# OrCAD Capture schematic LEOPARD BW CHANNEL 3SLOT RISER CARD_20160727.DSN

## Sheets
1 010 HISTORY: title: 010 HISTORY; rev: SA; company: Wiwynn Corporation; note: LEOPARD BDW RISER CARD; note: 8F, No.90, Xintai 5th Rd., Xizhi Dist,; note: New Taipei, Taiwan
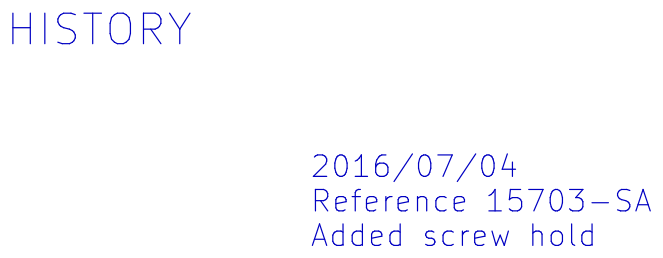
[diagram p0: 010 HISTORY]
2 009 P3V3_TPS53319: size A2; title: 009 P3V3_TPS53319; note: LEOPARD BW CHANNEL RISER CARD
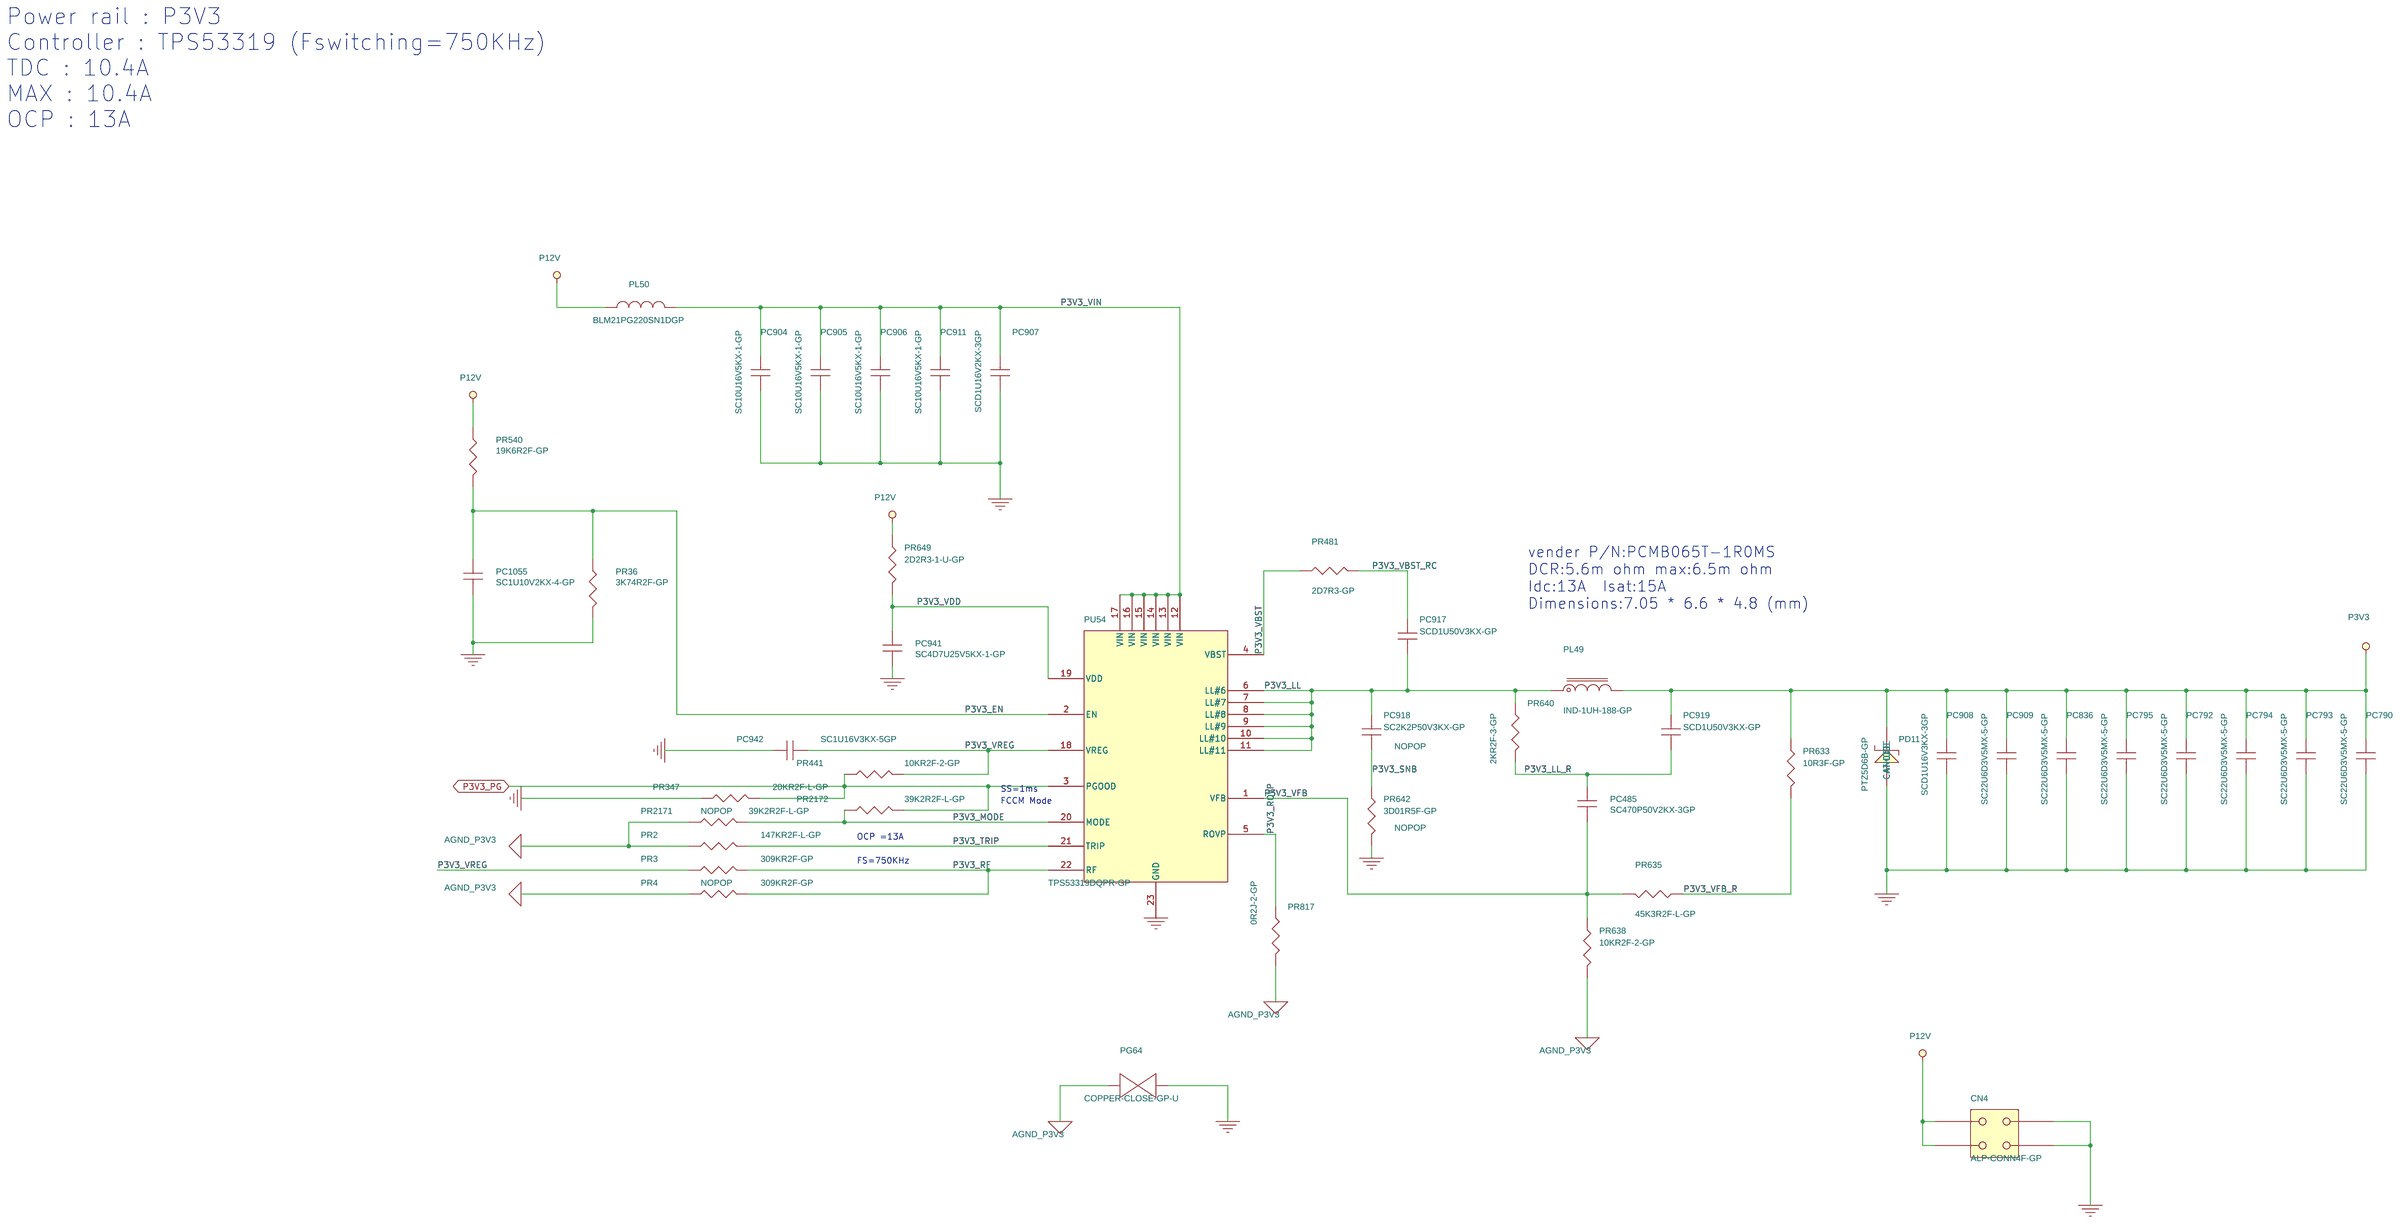
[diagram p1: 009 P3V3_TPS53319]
3 008 I2C-bus multiplexer: size A4; title: 008 I2C-Bus Multiplexer; note: LEOPARD BW CHANNEL RISER CARD
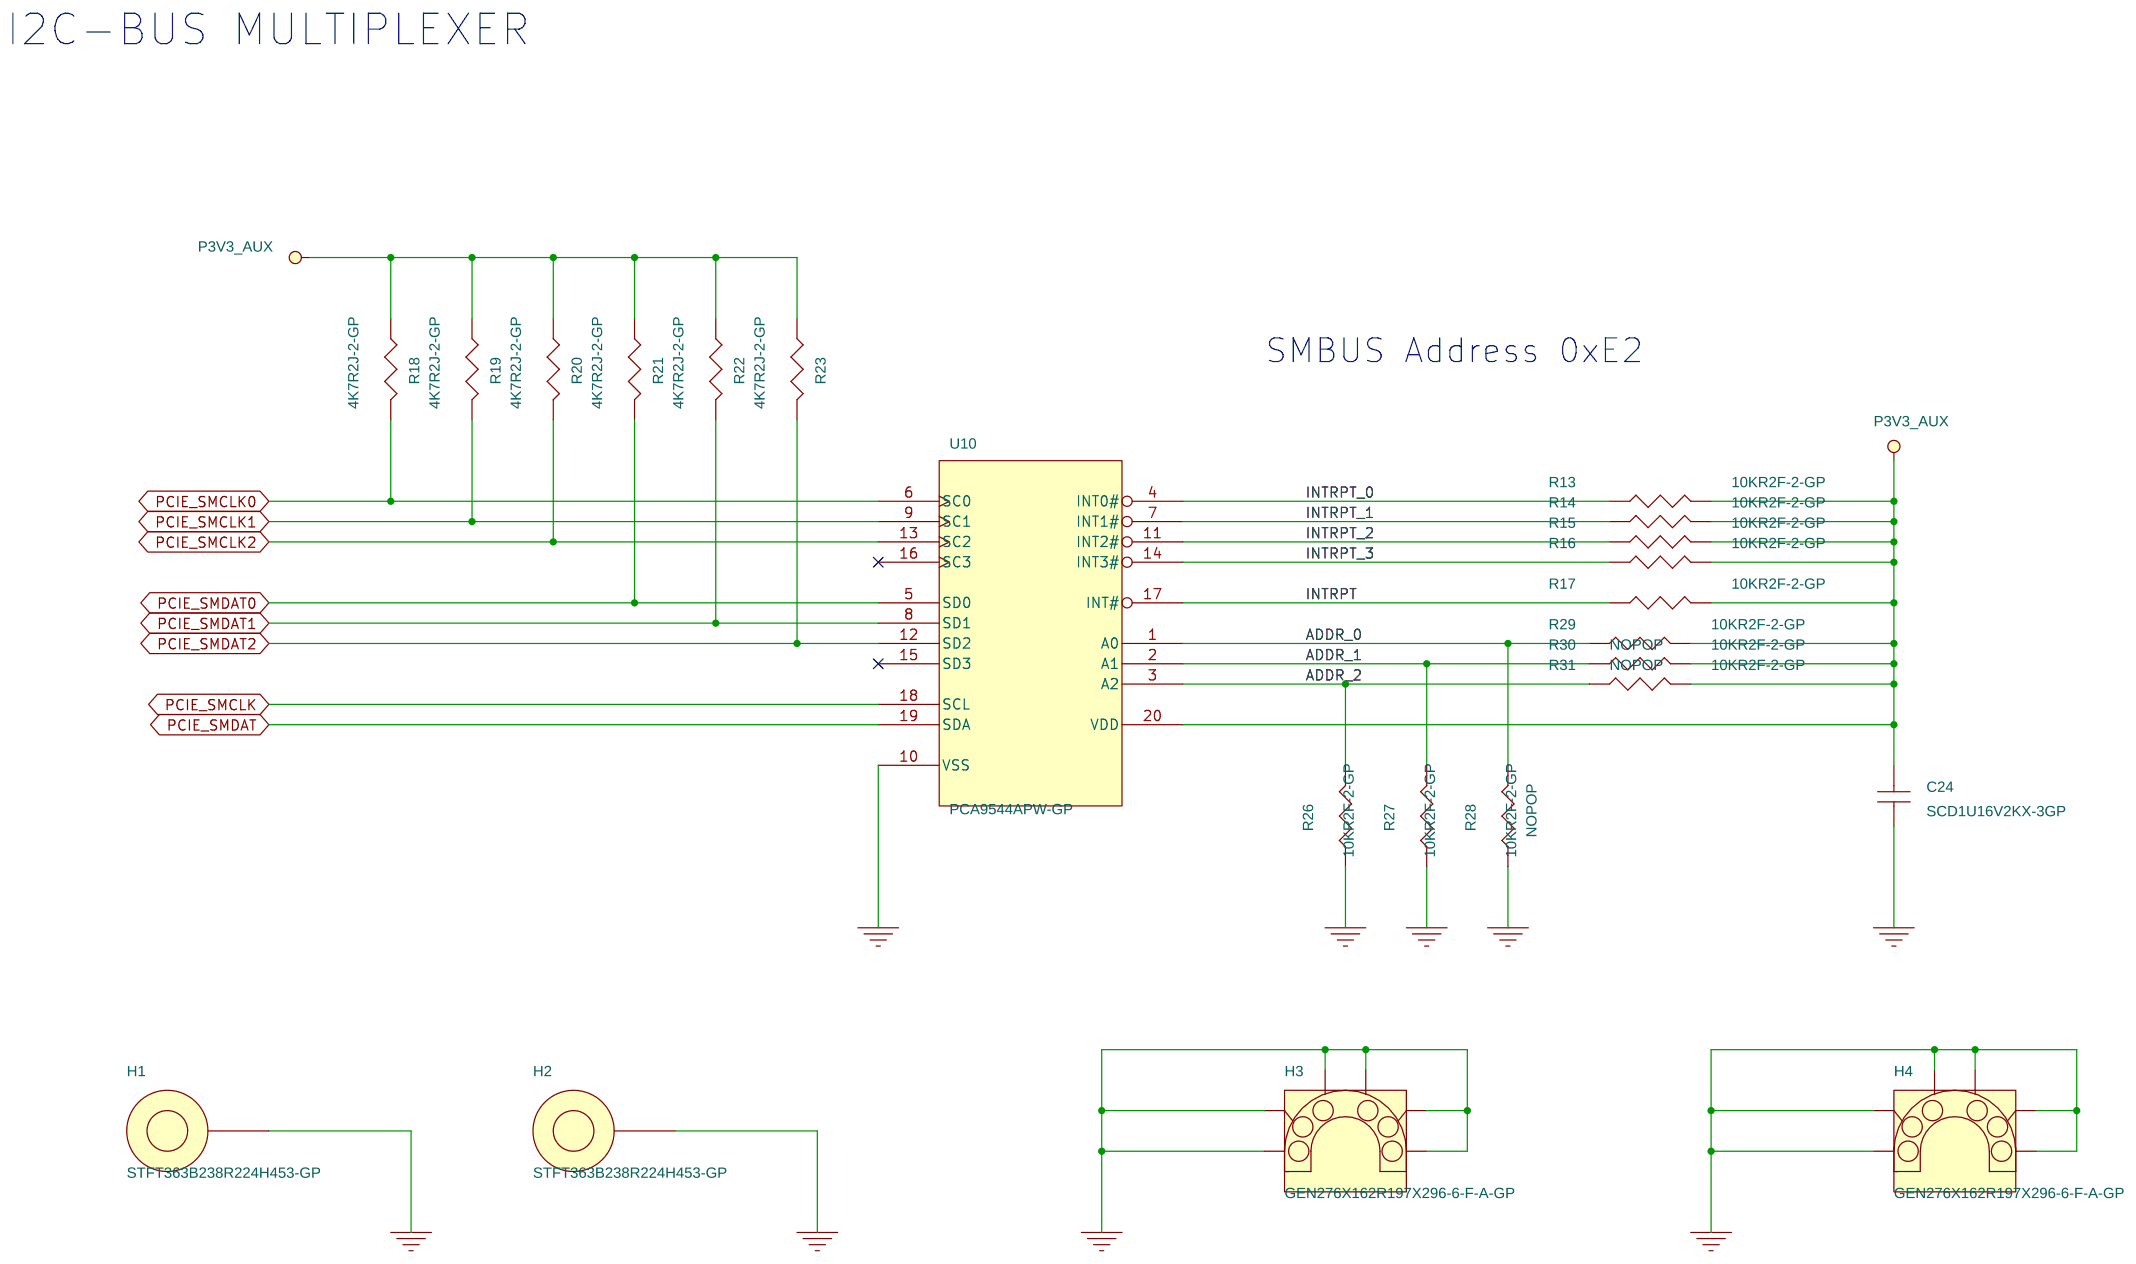
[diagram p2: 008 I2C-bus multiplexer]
4 007 PCIE X24 RISER GF: size A2; title: 007 PCIE X24 RISER GF; note: LEOPARD BW CHANNEL RISER CARD
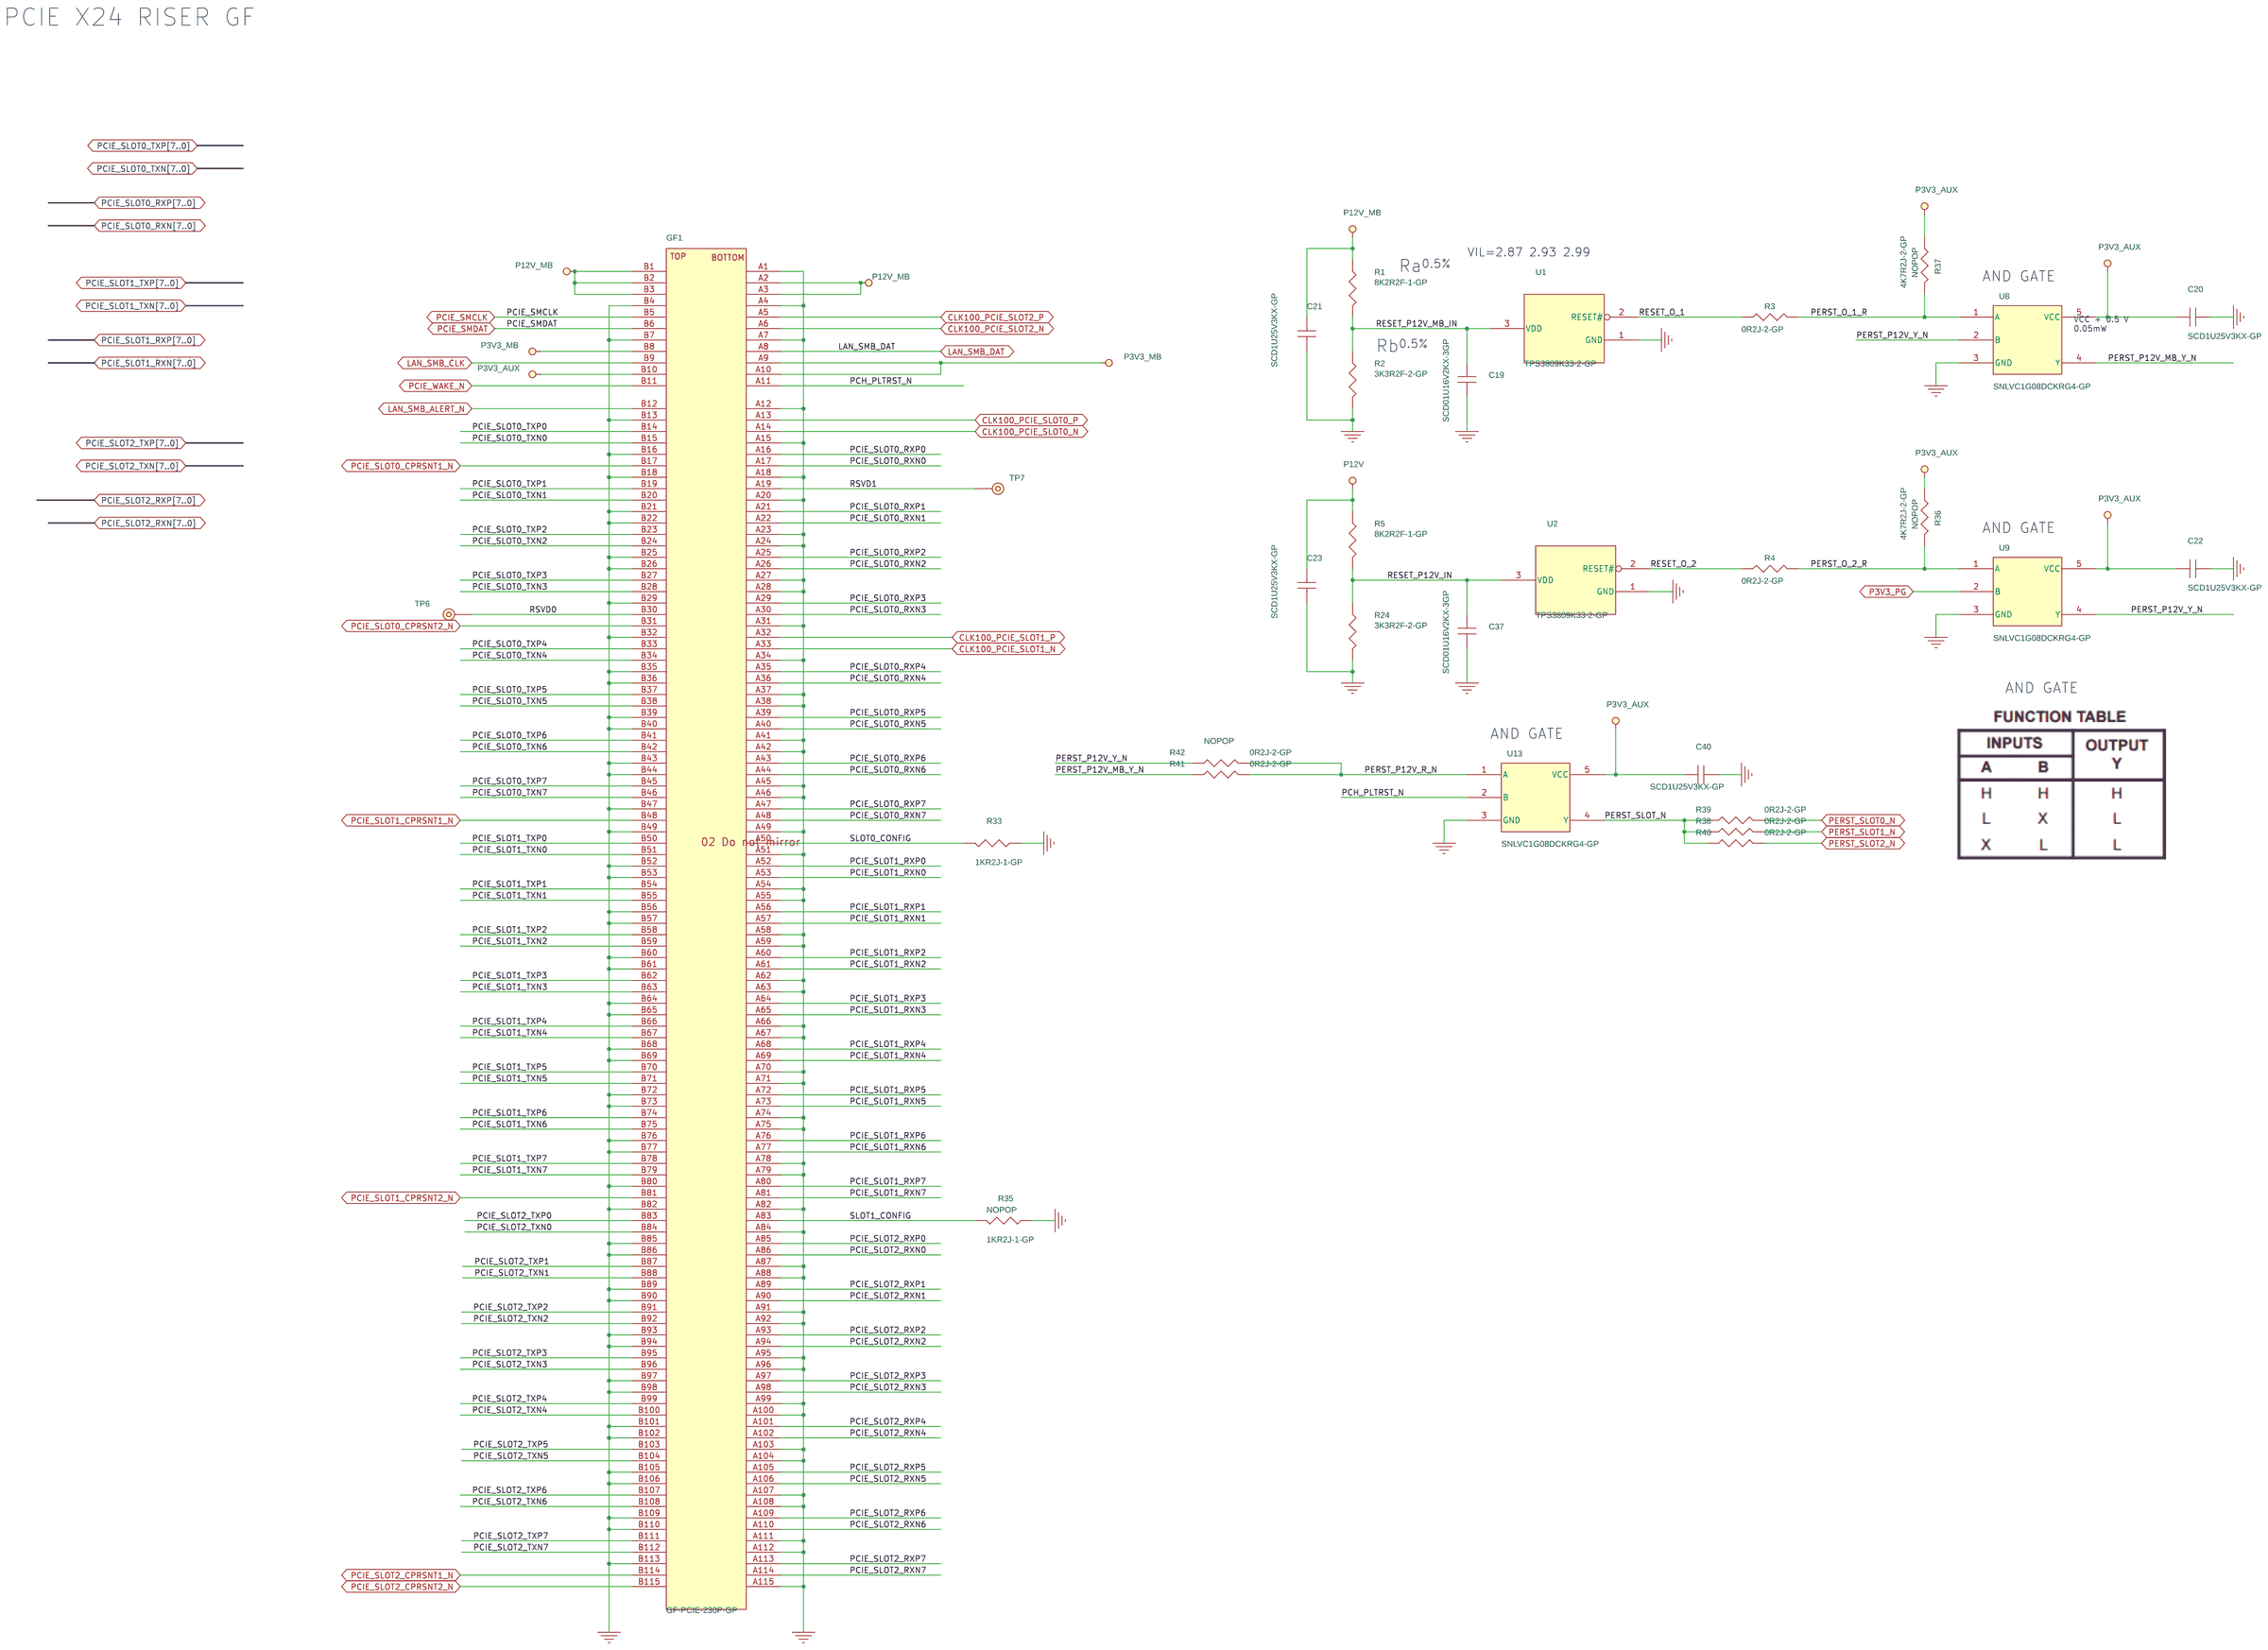
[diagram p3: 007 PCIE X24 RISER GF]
5 006 PCIE X8 RISER SLOT2: size A3; title: 006 PCIE X8 RISER SLOT4; note: LEOPARD BW CHANNEL RISER CARD
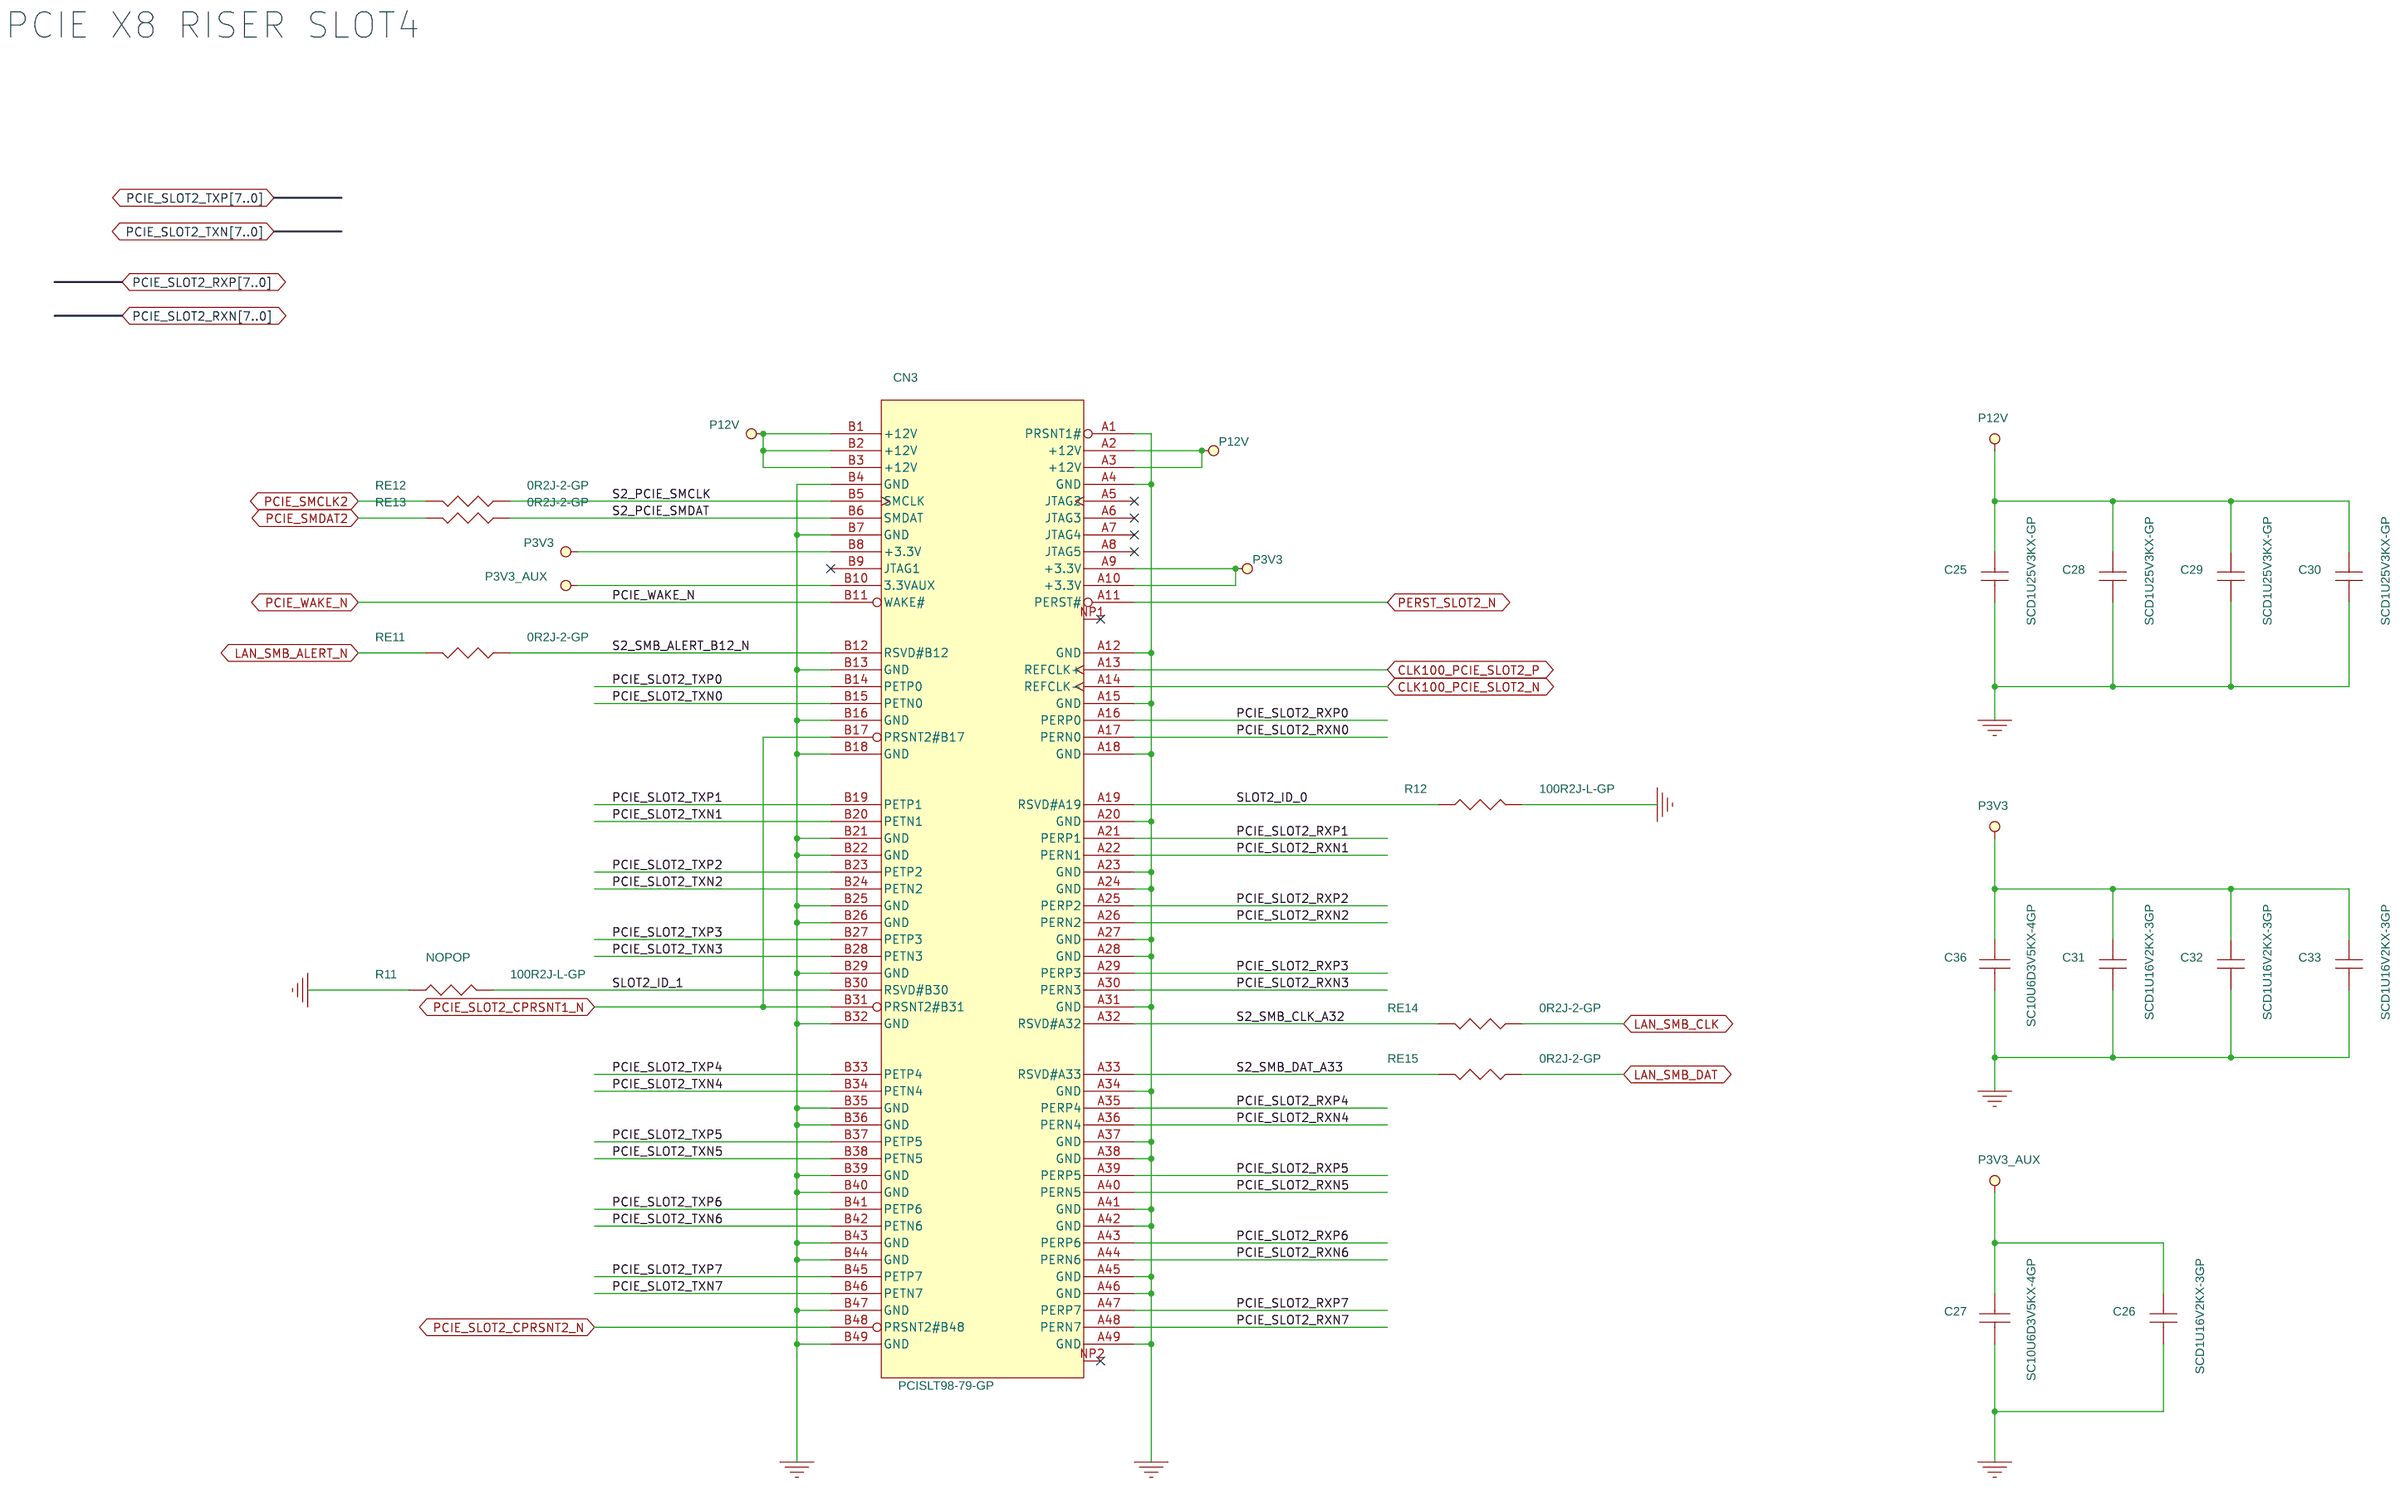
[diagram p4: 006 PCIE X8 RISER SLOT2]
6 005 PCIE X8 RISER SLOT1: size A3; title: 005 PCIE X8 RISER SLOT3; note: LEOPARD BW CHANNEL RISER CARD
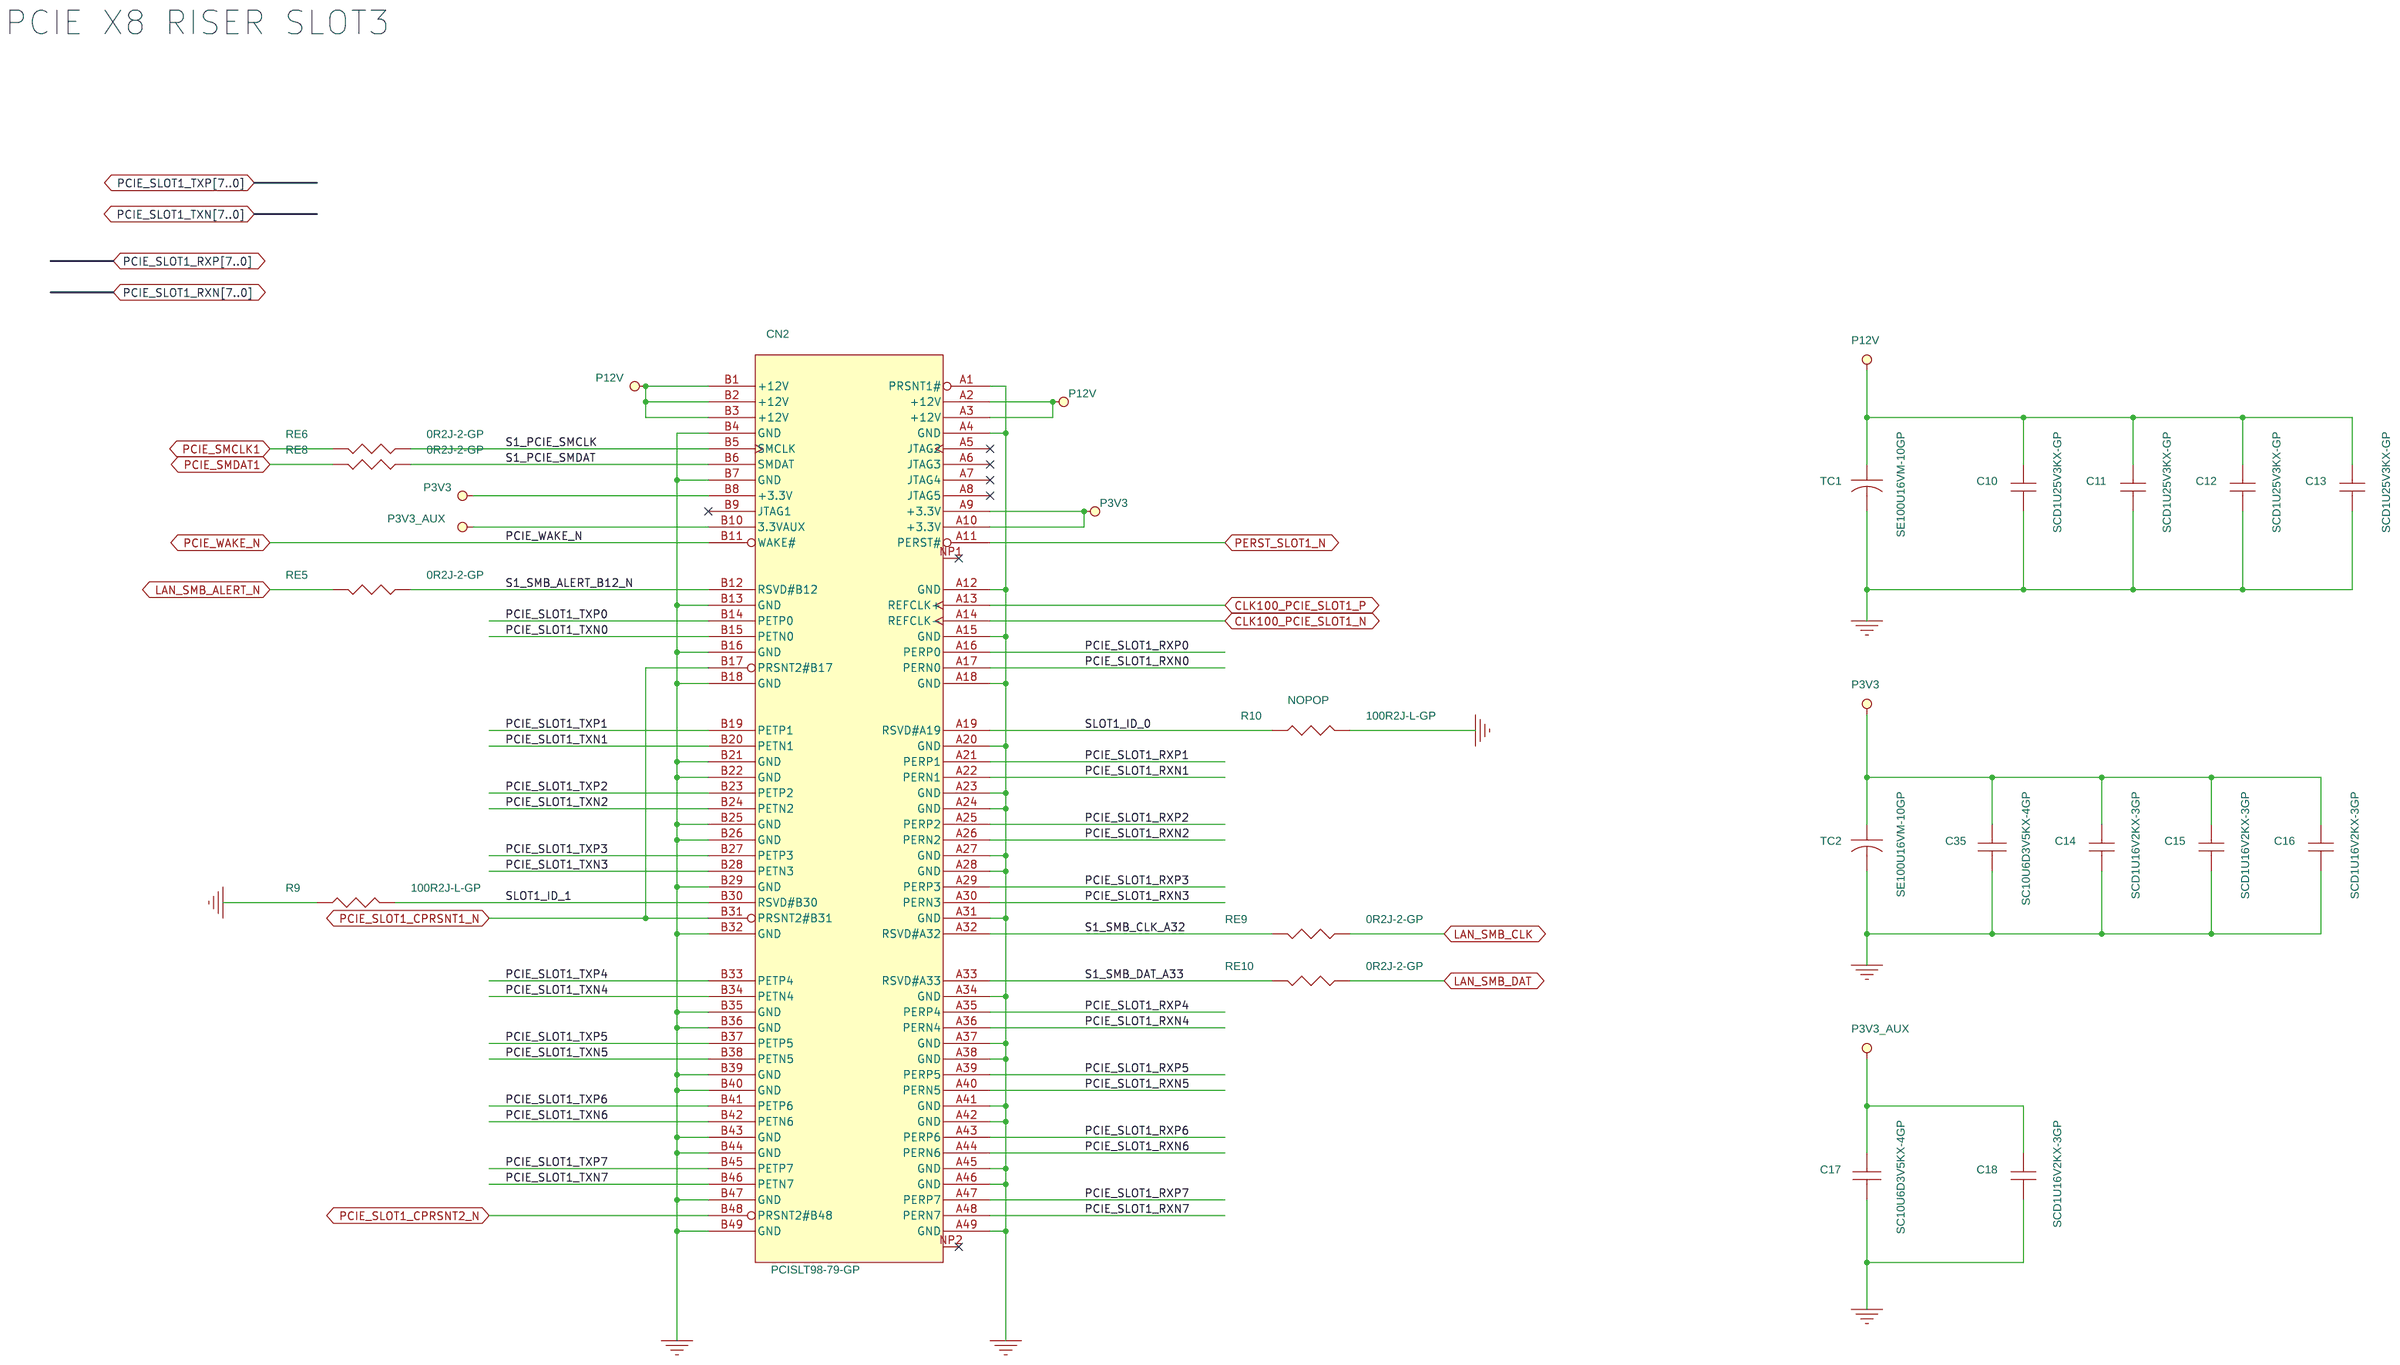
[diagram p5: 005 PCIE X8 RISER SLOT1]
7 004 PCIE X8 RISER SLOT0: size A3; title: 004 PCIE X8 RISER SLOT2; note: LEOPARD BW CHANNEL RISER CARD
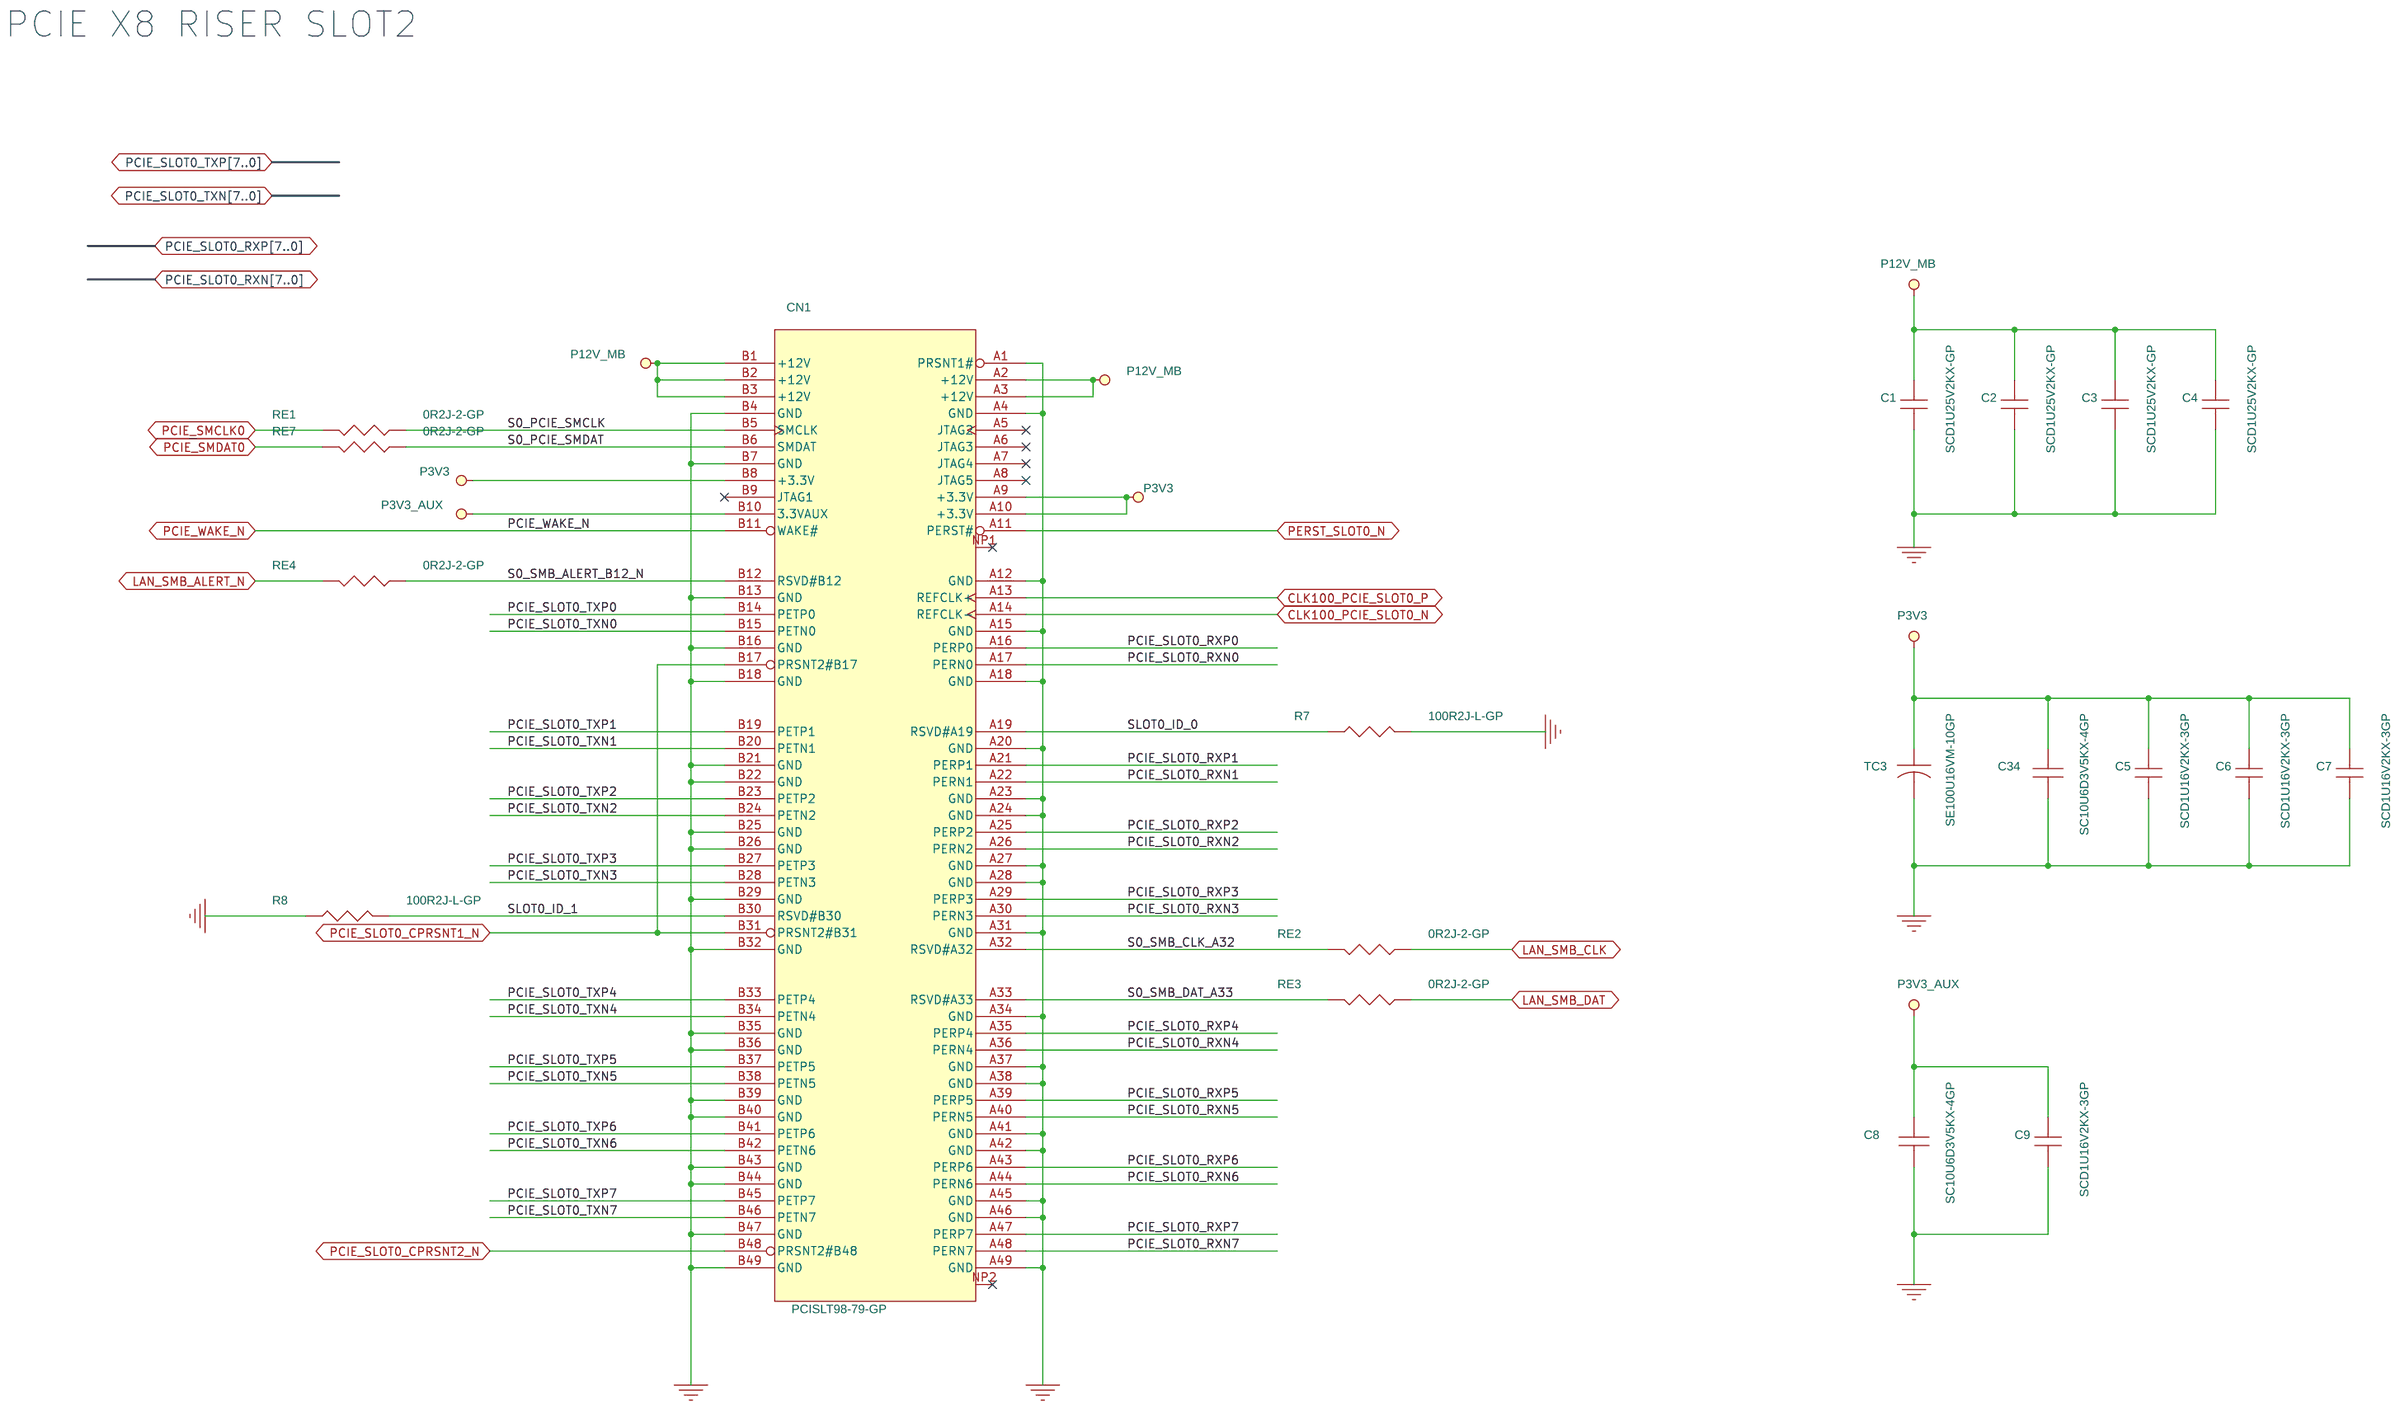
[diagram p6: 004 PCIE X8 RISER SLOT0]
8 003 STACKUP: title: 003 STACKUP; note: LEOPARD BW CHANNEL RISER CARD
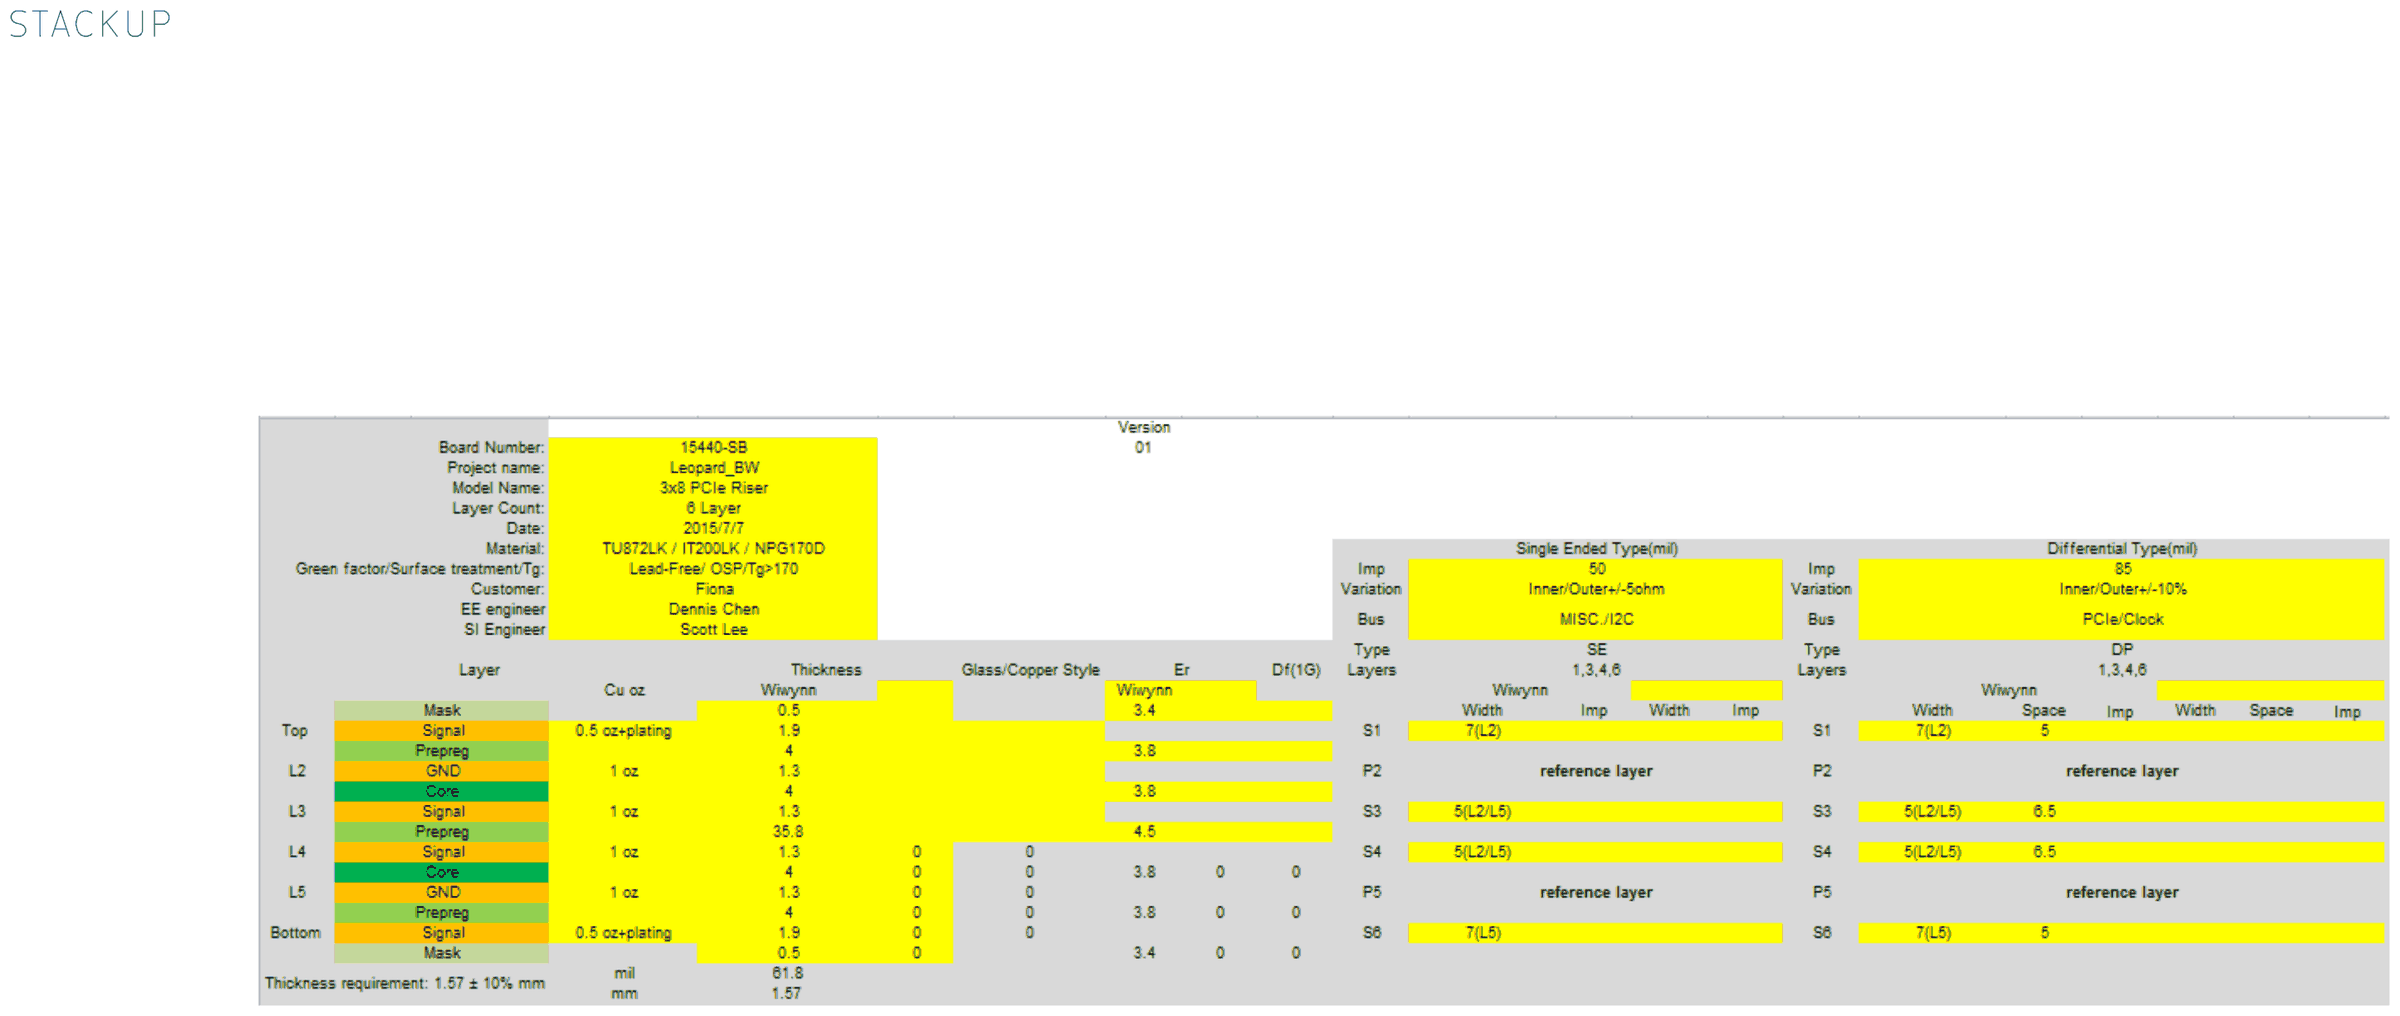
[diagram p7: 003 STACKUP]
9 002 BLOCK DIAGRAM: title: 002 BLOCK DIAGRAM; note: LEOPARD BW CHANNEL RISER CARD
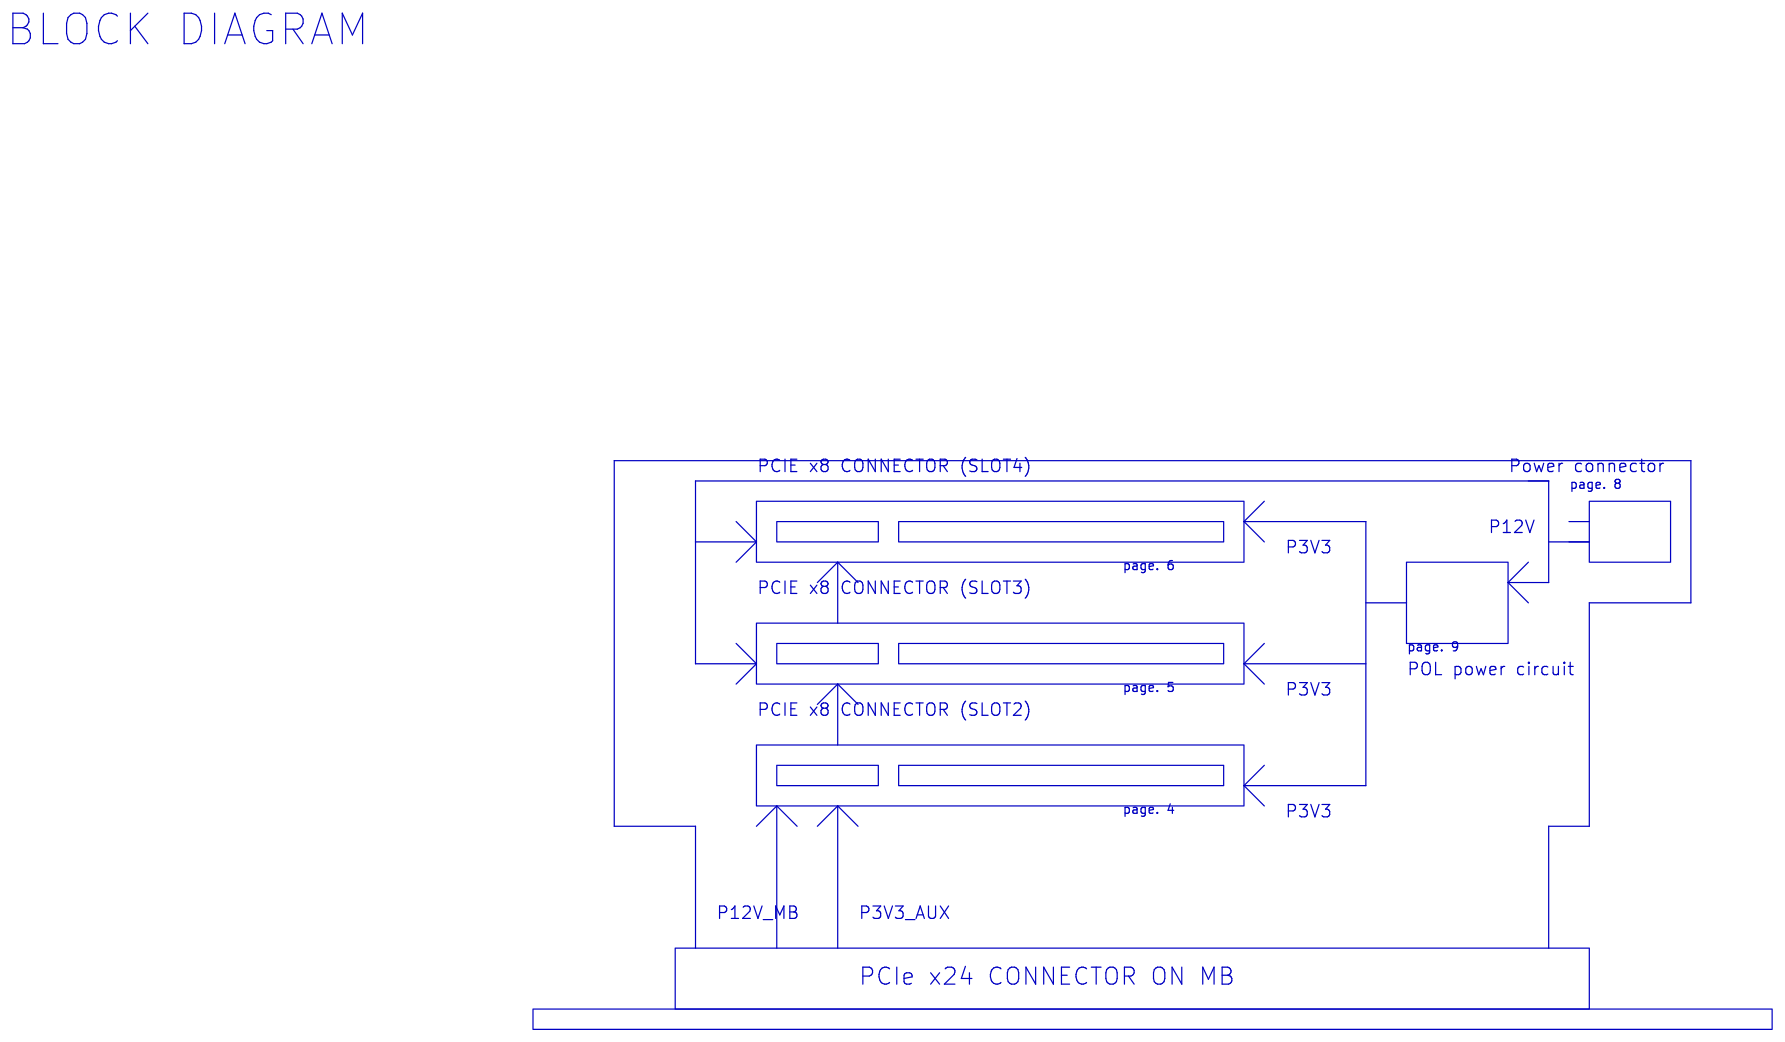
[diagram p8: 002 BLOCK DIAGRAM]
10 001 COVER PAGE: title: 001 COVER PAGE; note: LEOPARD BW CHANNEL RISER CARD
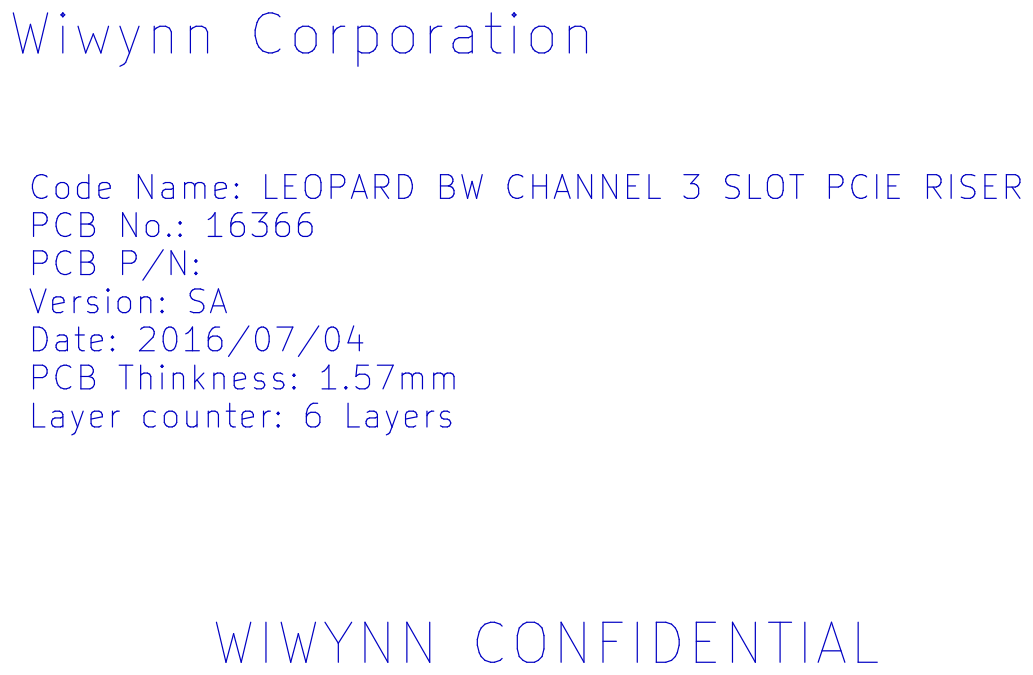
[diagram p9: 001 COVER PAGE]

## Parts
sheet 004 PCIE X8 RISER SLOT0
C1  SCD1U25V2KX-GP  [C402H22]
C2  SCD1U25V2KX-GP  [C402H22]
C3  SCD1U25V2KX-GP  [C402H22]
C4  SCD1U25V2KX-GP  [C402H22]
C5  SCD1U16V2KX-3GP  [C402H22]
C6  SCD1U16V2KX-3GP  [C402H22]
C7  SCD1U16V2KX-3GP  [C402H22]
C8  SC10U6D3V5KX-4GP  [C805H58]
C9  SCD1U16V2KX-3GP  [C402H22]
C34  SC10U6D3V5KX-4GP  [C805H58]
CN1  PCISLT98-79-GP  [G630H9811210TEU]
R7  100R2J-L-GP  [R402H15]
R8  100R2J-L-GP  [R402H15]
RE1  0R2J-2-GP  [R402H16]
RE2  0R2J-2-GP  [R402H16]
RE3  0R2J-2-GP  [R402H16]
RE4  0R2J-2-GP  [R402H16]
RE7  0R2J-2-GP  [R402H16]
TC3  SE100U16VM-10GP  [SE351618H217]
sheet 005 PCIE X8 RISER SLOT1
C10  SCD1U25V3KX-GP  [C603H36]
C11  SCD1U25V3KX-GP  [C603H36]
C12  SCD1U25V3KX-GP  [C603H36]
C13  SCD1U25V3KX-GP  [C603H36]
C14  SCD1U16V2KX-3GP  [C402H22]
C15  SCD1U16V2KX-3GP  [C402H22]
C16  SCD1U16V2KX-3GP  [C402H22]
C17  SC10U6D3V5KX-4GP  [C805H58]
C18  SCD1U16V2KX-3GP  [C402H22]
C35  SC10U6D3V5KX-4GP  [C805H58]
CN2  PCISLT98-79-GP  [G630H9811210TEU]
R9  100R2J-L-GP  [R402H15]
R10  100R2J-L-GP  [R402H15]
RE5  0R2J-2-GP  [R402H16]
RE6  0R2J-2-GP  [R402H16]
RE8  0R2J-2-GP  [R402H16]
RE9  0R2J-2-GP  [R402H16]
RE10  0R2J-2-GP  [R402H16]
TC1  SE100U16VM-10GP  [SE351618H217]
TC2  SE100U16VM-10GP  [SE351618H217]
sheet 006 PCIE X8 RISER SLOT2
C25  SCD1U25V3KX-GP  [C603H36]
C26  SCD1U16V2KX-3GP  [C402H22]
C27  SC10U6D3V5KX-4GP  [C805H58]
C28  SCD1U25V3KX-GP  [C603H36]
C29  SCD1U25V3KX-GP  [C603H36]
C30  SCD1U25V3KX-GP  [C603H36]
C31  SCD1U16V2KX-3GP  [C402H22]
C32  SCD1U16V2KX-3GP  [C402H22]
C33  SCD1U16V2KX-3GP  [C402H22]
C36  SC10U6D3V5KX-4GP  [C805H58]
CN3  PCISLT98-79-GP  [G630H9811210TEU]
R11  100R2J-L-GP  [R402H15]
R12  100R2J-L-GP  [R402H15]
RE11  0R2J-2-GP  [R402H16]
RE12  0R2J-2-GP  [R402H16]
RE13  0R2J-2-GP  [R402H16]
RE14  0R2J-2-GP  [R402H16]
RE15  0R2J-2-GP  [R402H16]
sheet 007 PCIE X24 RISER GF
C19  SCD01U16V2KX-3GP  [C402H22]
C20  SCD1U25V3KX-GP  [C603H36]
C21  SCD1U25V3KX-GP  [C603H36]
C22  SCD1U25V3KX-GP  [C603H36]
C23  SCD1U25V3KX-GP  [C603H36]
C37  SCD01U16V2KX-3GP  [C402H22]
C40  SCD1U25V3KX-GP  [C603H36]
GF1  GF-PCIE-230P-GP  [GF-PCIE-230P]
R1  8K2R2F-1-GP  [R402H16]
R2  3K3R2F-2-GP  [R402H16]
R3  0R2J-2-GP  [R402H16]
R4  0R2J-2-GP  [R402H16]
R5  8K2R2F-1-GP  [R402H16]
R24  3K3R2F-2-GP  [R402H16]
R33  1KR2J-1-GP  [R402H16]
R35  1KR2J-1-GP  [R402H16]
R36  4K7R2J-2-GP  [R402H16]
R37  4K7R2J-2-GP  [R402H16]
R38  0R2J-2-GP  [R402H16]
R39  0R2J-2-GP  [R402H16]
R40  0R2J-2-GP  [R402H16]
R41  0R2J-2-GP  [R402H16]
R42  0R2J-2-GP  [R402H16]
TP6  TPAD24  [TPAD24]
TP7  TPAD24  [TPAD24]
U1  TPS3809K33-2-GP  [SOT-23-1H58]
U2  TPS3809K33-2-GP  [SOT-23-1H58]
U8  SNLVC1G08DCKRG4-GP  [SC70-5H44]
U9  SNLVC1G08DCKRG4-GP  [SC70-5H44]
U13  SNLVC1G08DCKRG4-GP  [SC70-5H44]
sheet 008 I2C-bus multiplexer
C24  SCD1U16V2KX-3GP  [C402H22]
H1  STFT363B238R224H453-GP  [STFT363B238R224H453]
H2  STFT363B238R224H453-GP  [STFT363B238R224H453]
H3  GEN276X162R197X296-6-F-A-GP  [GEN276X162R197X296-6-F-A]
H4  GEN276X162R197X296-6-F-A-GP  [GEN276X162R197X296-6-F-A]
R13  10KR2F-2-GP  [R402H16]
R14  10KR2F-2-GP  [R402H16]
R15  10KR2F-2-GP  [R402H16]
R16  10KR2F-2-GP  [R402H16]
R17  10KR2F-2-GP  [R402H16]
R18  4K7R2J-2-GP  [R402H16]
R19  4K7R2J-2-GP  [R402H16]
R20  4K7R2J-2-GP  [R402H16]
R21  4K7R2J-2-GP  [R402H16]
R22  4K7R2J-2-GP  [R402H16]
R23  4K7R2J-2-GP  [R402H16]
R26  10KR2F-2-GP  [R402H16]
R27  10KR2F-2-GP  [R402H16]
R28  10KR2F-2-GP  [R402H16]
R29  10KR2F-2-GP  [R402H16]
R30  10KR2F-2-GP  [R402H16]
R31  10KR2F-2-GP  [R402H16]
U10  PCA9544APW-GP  [TSOIC20H44]
sheet 009 P3V3_TPS53319
CN4  ALP-CONN4F-GP  [C23118-P04C0-L]
PC485  SC470P50V2KX-3GP  [C402H22]
PC790  SC22U6D3V5MX-5-GP  [C805H56]
PC792  SC22U6D3V5MX-5-GP  [C805H56]
PC793  SC22U6D3V5MX-5-GP  [C805H56]
PC794  SC22U6D3V5MX-5-GP  [C805H56]
PC795  SC22U6D3V5MX-5-GP  [C805H56]
PC836  SC22U6D3V5MX-5-GP  [C805H56]
PC904  SC10U16V5KX-1-GP  [C805H54]
PC905  SC10U16V5KX-1-GP  [C805H54]
PC906  SC10U16V5KX-1-GP  [C805H54]
PC907  SCD1U16V2KX-3GP  [C402H22]
PC908  SCD1U16V3KX-3GP  [C603H36]
PC909  SC22U6D3V5MX-5-GP  [C805H56]
PC911  SC10U16V5KX-1-GP  [C805H54]
PC917  SCD1U50V3KX-GP  [C603H36]
PC918  SC2K2P50V3KX-GP  [C603]
PC919  SCD1U50V3KX-GP  [C603H36]
PC941  SC4D7U25V5KX-1-GP  [C805H58]
PC942  SC1U16V3KX-5GP  [C603H36]
PC1055  SC1U10V2KX-4-GP  [C402H22]
PD11  PTZ5D6B-GP  [D502715AKH87]
PG64  COPPER-CLOSE-GP-U  [CON2C-U]
PL49  IND-1UH-188-GP  [L7166-1830-UH197]
PL50  BLM21PG220SN1DGP  [L20125H42]
PR2  147KR2F-L-GP  [R402H16]
PR3  309KR2F-GP  [R402H16]
PR4  309KR2F-GP  [R402H16]
PR36  3K74R2F-GP  [R402H16]
PR347  20KR2F-L-GP  [R402H16]
PR441  10KR2F-2-GP  [R402H16]
PR481  2D7R3-GP  [R603H22]
PR540  19K6R2F-GP  [R402H16]
PR633  10R3F-GP  [R603H22]
PR635  45K3R2F-L-GP  [R402H16]
PR638  10KR2F-2-GP  [R402H16]
PR640  2KR2F-3-GP  [R402H16]
PR642  3D01R5F-GP  [R805H24]
PR649  2D2R3-1-U-GP  [R603H22]
PR817  0R2J-2-GP  [R402H16]
PR2171  39K2R2F-L-GP  [R402H16]
PR2172  39K2R2F-L-GP  [R402H16]
PU54  TPS53319DQPR-GP  [QFN22G6050-G6133H60]

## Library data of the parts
C1-C4 = SCD1U25V2KX-GP: CHIP CAP C 0.1U 25V K0402 X5R; CATEGORIES: CAP_1.xV; Category: SATA; GREENDFACTOR: R2_SA;HF_SA;G_SA;; MAIN_SOURCE: M; POP?: POP; Part Number: 78.10422.5FL; Part Type: SMD-BCG1; SPEC: http://wpqssvr.wistron.com.tw:7001/wpqs/servlet/COM.qpart.Attachment?PartNumber=78.10422.5FL
C5-C7 C9 C14-C16 C18 C26 C31-C33 = SCD1U16V2KX-3GP: CHIP CAP C 0.1U 16V K0402 X7R; CATEGORIES: CAP_1.xV; GREENDFACTOR: R2_SA;HF_SA;G_SA;; MAIN_SOURCE: M; POP?: POP; Package Type: SMD-BCG; Part Number: 78.10421.2FL; SPEC: http://wpqssvr.wistron.com.tw:7001/wpqs/servlet/COM.qpart.Attachment?PartNumber=78.10421.2FL
C8 C17 C27 C34-C36 = SC10U6D3V5KX-4GP: CHIP CAP C 10U 6.3V K0805 X7R; GREENDFACTOR: R2_SA;HF_SA;G_SA;; POP?: POP; Package Type: SMD-BCG; Part Number: 78.10620.21L; SPEC: http://wpqssvr.wistron.com.tw:7001/wpqs/servlet/COM.qpart.Attachment?PartNumber=78.10620.21L
CN1-CN3 = PCISLT98-79-GP: CONN EDGE DIP 98P G630H9811210TEU; GREENDFACTOR: R2_C;; Part Number: 020.50107.0098; Part Type: CONN-G7; SPEC: http://wpqssvr.wistron.com.tw:7001/wpqs/servlet/COM.qpart.Attachment?PartNumber=020.50107.0098
R7-R9 R12 = 100R2J-L-GP: CHIP RES 100 J 1/16W 0402 13" REEL; GREENDFACTOR: R2_SA;HF_SA;G_SA;; POP?: POP; Package Type: SMD-RG5; Part Number: 63.10134.L0L; SPEC: http://wpqssvr.wistron.com.tw:7001/wpqs/servlet/COM.qpart.Attachment?PartNumber=63.10134.L0L
RE1-RE15 = 0R2J-2-GP: CHIP RES 0 J 1/16W 0402; Category: CPLD; GREENDFACTOR: R2_SA;HF_SA;G_SA;; POP?: POP; Part Number: 63.R0034.1DL; Part Type: SMD-RG; SPEC: http://wpqssvr.wistron.com.tw:7001/wpqs/servlet/COM.qpart.Attachment?PartNumber=63.R0034.1DL
TC1-TC3 = SE100U16VM-10GP: CHIP CAP EL 100U 16V M 6.3*5.4; GREENDFACTOR: R2_SA;; Part Number: 79.1071D.3AL; Part Type: SMD-TCG; SPEC: http://wpqssvr.wistron.com.tw:7001/wpqs/servlet/COM.qpart.Attachment?PartNumber=79.1071D.3AL
C10-C13 C25 C28-C30 = SCD1U25V3KX-GP: CHIP CAP C 0.1U 25V K0603 X7R; CATEGORIES: CAP_1.xV; GREENDFACTOR: R2_SA;HF_SA;G_SA;; MAIN_SOURCE: M; Part Number: 78.10422.2BL; Part Type: RCL_GP; SPEC: http://wpqssvr.wistron.com.tw:7001/wpqs/servlet/COM.qpart.Attachment?PartNumber=78.10422.2BL
R10 R11 = 100R2J-L-GP: CHIP RES 100 J 1/16W 0402 13" REEL; GREENDFACTOR: R2_SA;HF_SA;G_SA;; POP?: NOPOP; Package Type: SMD-RG5; Part Number: 63.10134.L0L; SPEC: http://wpqssvr.wistron.com.tw:7001/wpqs/servlet/COM.qpart.Attachment?PartNumber=63.10134.L0L
C19 C37 = SCD01U16V2KX-3GP: CHIP CAP C 0.01U 16V K0402 X7R; CATEGORIES: CAP_3V/5V; GREENDFACTOR: R2_SA;HF_SA;G_SA;; MAIN_SOURCE: M; Part Number: 78.10321.2FL; Part Type: SMD-BCG; SPEC: http://wpqssvr.wistron.com.tw:7001/wpqs/servlet/COM.qpart.Attachment?PartNumber=78.10321.2FL
C20 = SCD1U25V3KX-GP: CHIP CAP C 0.1U 25V K0603 X7R; CATEGORIES: CAP_1.xV; GREENDFACTOR: R2_SA;R_SA;HF_SA;G_SA;; MAIN_SOURCE: M; Package Type: RCL_GP; Part Number: 78.10422.2BL; SPEC: http://wpqssvr.wistron.com.tw:7001/wpqs/servlet/COM.qpart.Attachment?PartNumber=78.10422.2BL
C21 = SCD1U25V3KX-GP: CHIP CAP C 0.1U 25V K0603 X7R; CATEGORIES: CAP_1.xV; GREENDFACTOR: R2_SA;HF_SA;G_SA;; MAIN_SOURCE: M; Package Type: RCL_GP; Part Number: 78.10422.2BL; SPEC: http://wpqssvr.wistron.com.tw:7001/wpqs/servlet/COM.qpart.Attachment?PartNumber=78.10422.2BL
C22 C40 = SCD1U25V3KX-GP: CHIP CAP C 0.1U 25V K0603 X7R; CATEGORIES: CAP_1.xV; GREENDFACTOR: R2_SA;R_SA;HF_SA;G_SA;; MAIN_SOURCE: M; POP?: POP; Package Type: RCL_GP; Part Number: 78.10422.2BL; SPEC: http://wpqssvr.wistron.com.tw:7001/wpqs/servlet/COM.qpart.Attachment?PartNumber=78.10422.2BL
C23 = SCD1U25V3KX-GP: CHIP CAP C 0.1U 25V K0603 X7R; CATEGORIES: CAP_1.xV; GREENDFACTOR: R2_SA;HF_SA;G_SA;; MAIN_SOURCE: M; POP?: POP; Package Type: RCL_GP; Part Number: 78.10422.2BL; SPEC: http://wpqssvr.wistron.com.tw:7001/wpqs/servlet/COM.qpart.Attachment?PartNumber=78.10422.2BL
GF1 = GF-PCIE-230P-GP: PCIE GOLD FINGURE 230P; GREENDFACTOR: R2_C;; Package Type: CONN-G7; Part Number: ZZ.GF001.711; SPEC: http://wpqssvr.wistron.com.tw:7001/wpqs/servlet/COM.qpart.Attachment?PartNumber=ZZ.GF001.711
R1 R5 = 8K2R2F-1-GP: CHIP RES 8.2K F 1/16W 0402; GREENDFACTOR: R2_SA;HF_SA;G_SA;; Part Number: 64.82015.6DL; Part Type: SMD-RG; SPEC: http://wpqssvr.wistron.com.tw:7001/wpqs/servlet/COM.qpart.Attachment?PartNumber=64.82015.6DL
R2 R24 = 3K3R2F-2-GP: CHIP RES 3.3K F 1/16W 0402; GREENDFACTOR: R2_SA;HF_SA;G_SA;; Part Number: 64.33015.6DL; Part Type: SMD-RG; SPEC: http://wpqssvr.wistron.com.tw:7001/wpqs/servlet/COM.qpart.Attachment?PartNumber=64.33015.6DL
R3 R4 R38-R41 = 0R2J-2-GP: CHIP RES 0 J 1/16W 0402; Category: HOTPLUG_CONTROL; GREENDFACTOR: R2_SA;HF_SA;G_SA;; Package Type: SMD-RG; Part Number: 63.R0034.1DL; Part Type: SMD-RG; SPEC: http://wpqssvr.wistron.com.tw:7001/wpqs/servlet/COM.qpart.Attachment?PartNumber=63.R0034.1DL
R33 = 1KR2J-1-GP: CHIP RES 1K J 1/16W 0402; Belong: POP; Category: PCH; GREENDFACTOR: R2_SA;HF_SA;G_SA;; POP?: POP; Package Type: SMD-RG; Part Number: 63.10234.1DL; Part Type: SMD-RG; SPEC: http://wpqssvr.wistron.com.tw:7001/wpqs/servlet/COM.qpart.Attachment?PartNumber=63.10234.1DL
R35 = 1KR2J-1-GP: CHIP RES 1K J 1/16W 0402; Belong: POP; Category: PCH; GREENDFACTOR: R2_SA;HF_SA;G_SA;; POP?: NOPOP; Package Type: SMD-RG; Part Number: 63.10234.1DL; Part Type: SMD-RG; SPEC: http://wpqssvr.wistron.com.tw:7001/wpqs/servlet/COM.qpart.Attachment?PartNumber=63.10234.1DL
R36 R37 = 4K7R2J-2-GP: CHIP RES 4.7K J 1/16W 0402; GREENDFACTOR: R2_SA;HF_SA;G_SA;; POP?: NOPOP; Part Number: 63.47234.1DL; Part Type: SMD-RG; SPEC: http://wpqssvr.wistron.com.tw:7001/wpqs/servlet/COM.qpart.Attachment?PartNumber=63.47234.1DL
R42 = 0R2J-2-GP: CHIP RES 0 J 1/16W 0402; Category: HOTPLUG_CONTROL; GREENDFACTOR: R2_SA;HF_SA;G_SA;; POP?: NOPOP; Package Type: SMD-RG; Part Number: 63.R0034.1DL; Part Type: SMD-RG; SPEC: http://wpqssvr.wistron.com.tw:7001/wpqs/servlet/COM.qpart.Attachment?PartNumber=63.R0034.1DL
TP6 TP7 = TPAD24: 24 MILS TEST PAD; GREENDFACTOR: Regular;; Package Type: DISCRET2; Part Number: ZZ.PAD24.001; SPEC: http://wpqssvr.wistron.com.tw:7001/wpqs/servlet/COM.qpart.Attachment?PartNumber=ZZ.PAD24.001
U1 U2 = TPS3809K33-2-GP: IC RESET TPS3809K33DBVT SOT-23; GREENDFACTOR: R2_SA;; Package Type: DISCRET-G; Part Number: 74.03809.07B; SPEC: http://wpqssvr.wistron.com.tw:7001/wpqs/servlet/COM.qpart.Attachment?PartNumber=74.03809.07B
U8 = SNLVC1G08DCKRG4-GP: IC CMOS SN74LVC1G08DCKRG4 DCK; GREENDFACTOR: R_SA;G_SA;; Package Type: TTL-G; Part Number: 73.01G08.DHG; SPEC: http://wpqssvr.wistron.com.tw:7001/wpqs/servlet/COM.qpart.Attachment?PartNumber=73.01G08.DHG
U9 U13 = SNLVC1G08DCKRG4-GP: IC CMOS SN74LVC1G08DCKRG4 DCK; GREENDFACTOR: R_SA;G_SA;; POP?: POP; Package Type: TTL-G; Part Number: 73.01G08.DHG; SPEC: http://wpqssvr.wistron.com.tw:7001/wpqs/servlet/COM.qpart.Attachment?PartNumber=73.01G08.DHG
C24 = SCD1U16V2KX-3GP: CHIP CAP C 0.1U 16V K0402 X7R; CATEGORIES: CAP_1.xV; GREENDFACTOR: R2_SA;HF_SA;G_SA;; MAIN_SOURCE: M; Part Number: 78.10421.2FL; Part Type: SMD-BCG; SPEC: http://wpqssvr.wistron.com.tw:7001/wpqs/servlet/COM.qpart.Attachment?PartNumber=78.10421.2FL
H1 H2 = STFT363B238R224H453-GP: THUMB SCREW SMT M3X0.5 L4.6; GREENDFACTOR: R2_C;; Part Number: 086.2AT24.04R6; Part Type: DISCRET-GC1; SPEC: http://wpqssvr.wistron.com.tw:7001/wpqs/servlet/COM.qpart.Attachment?PartNumber=086.2AT24.04R6
H3 H4 = GEN276X162R197X296-6-F-A-GP: SCREW HOLE TYPE A; GREENDFACTOR: R2_C;; Part Number: ZZ.SCREW.511; Part Type: DISCRET-G8; SPEC: http://wpqssvr.wistron.com.tw:7001/wpqs/servlet/COM.qpart.Attachment?PartNumber=ZZ.SCREW.511
R13-R17 R26 R27 R29 = 10KR2F-2-GP: CHIP RES 10K F 1/16W 0402; GREENDFACTOR: R2_SA;HF_SA;G_SA;; Part Number: 64.10025.6DL; Part Type: SMD-RG; SPEC: http://wpqssvr.wistron.com.tw:7001/wpqs/servlet/COM.qpart.Attachment?PartNumber=64.10025.6DL
R18-R23 = 4K7R2J-2-GP: CHIP RES 4.7K J 1/16W 0402; GREENDFACTOR: R2_SA;HF_SA;G_SA;; Part Number: 63.47234.1DL; Part Type: SMD-RG; SPEC: http://wpqssvr.wistron.com.tw:7001/wpqs/servlet/COM.qpart.Attachment?PartNumber=63.47234.1DL
R28 R30 R31 = 10KR2F-2-GP: CHIP RES 10K F 1/16W 0402; GREENDFACTOR: R2_SA;HF_SA;G_SA;; POP?: NOPOP; Part Number: 64.10025.6DL; Part Type: SMD-RG; SPEC: http://wpqssvr.wistron.com.tw:7001/wpqs/servlet/COM.qpart.Attachment?PartNumber=64.10025.6DL
U10 = PCA9544APW-GP: IC CTRL PCA9544APW TSSOP 20P; GREENDFACTOR: R2_SA;; Part Number: 71.09544.A0W; Part Type: DISCRET-G; SPEC: c
CN4 = ALP-CONN4F-GP: CONN CTR 4P C23118-P04C0-L, PA9T; GREENDFACTOR: R2_C;; Part Number: 020.80390.0004; Part Type: CONN-G5; SPEC: http://wpqssvr.wistron.com.tw:7001/wpqs/servlet/COM.qpart.Attachment?PartNumber=020.80390.0004
PC485 = SC470P50V2KX-3GP: CHIP CAP 470P50V K0402 X7R(ROH; CATEGORIES: CAP_Small; GREENDFACTOR: R2_SA;HF_SA;G_SA;; MAIN_SOURCE: M; Package Type: SMD-BCG; Part Number: 78.47124.2FL; SPEC: http://wpqssvr.wistron.com.tw:7001/wpqs/servlet/COM.qpart.Attachment?PartNumber=78.47124.2FL
PC790 PC792-PC795 PC836 PC909 = SC22U6D3V5MX-5-GP: CHIP CAP C 22U 6.3V M0805 X6S; GREENDFACTOR: R2_SA;HF_SA;G_SA;; Package Type: SMD-BCG2; Part Number: 78.22610.81L; SPEC: http://wpqssvr.wistron.com.tw:7001/wpqs/servlet/COM.qpart.Attachment?PartNumber=78.22610.81L
PC904-PC906 PC911 = SC10U16V5KX-1-GP: CHIP CAP C 10U 16V K0805 X6S; GREENDFACTOR: R2_SA;; Package Type: SMD-BCG5; Part Number: 78.10621.81L; SPEC: http://wpqssvr.wistron.com.tw:7001/wpqs/servlet/COM.qpart.Attachment?PartNumber=78.10621.81L
PC907 = SCD1U16V2KX-3GP: CHIP CAP C 0.1U 16V K0402 X7R; GREENDFACTOR: R2_SA;HF_SA;G_SA;; MAIN_SOURCE: M; Package Type: SMD-BCG; Part Number: 78.10421.2FL; SPEC: http://wpqssvr.wistron.com.tw:7001/wpqs/servlet/COM.qpart.Attachment?PartNumber=78.10421.2FL
PC908 = SCD1U16V3KX-3GP: CHIP CAP 0.1U16V K0603 X7R(ROH; GREENDFACTOR: R2_SA;R_SA;HF_SA;G_SA;; Module: VR_SYSTEM_P1V8; Package Type: SMD-BCG; Part Number: 78.10421.2BL; SPEC: http://wpqssvr.wistron.com.tw:7001/wpqs/servlet/COM.qpart.Attachment?PartNumber=78.10421.2BL; Size: 0603; Type: X7R
PC917 PC919 = SCD1U50V3KX-GP: CHIP CAP C 0.1U 50V K0603 X7R; GREENDFACTOR: R2_SA;HF_SA;G_SA;; Level: SMD; MAIN_SOURCE: M; Package Type: RCL_GP; Part Number: 78.10424.2BL; Part Type: RCL_GP; SPEC: http://wpqssvr.wistron.com.tw:7001/wpqs/servlet/COM.qpart.Attachment?PartNumber=78.10424.2BL; Status: POP
PC918 = SC2K2P50V3KX-GP: CHIP CAP C 2200P 50V K0603 X7R; GREENDFACTOR: R2_SA;HF_SA;G_SA;; Level: SMD; POP?: NOPOP; Package Type: SMD-BCG6; Part Number: 78.22224.2BL; Part Type: SMD-BCG6; SPEC: http://wpqssvr.wistron.com.tw:7001/wpqs/servlet/COM.qpart.Attachment?PartNumber=78.22224.2BL
PC941 = SC4D7U25V5KX-1-GP: CHIP CAP C 4.7U 25V K0805 X7R; GREENDFACTOR: R2_SA;HF_SA;G_SA;; Package Type: SMD-BCG4; Part Number: 078.47522.0211; SPEC: http://wpqssvr.wistron.com.tw:7001/wpqs/servlet/COM.qpart.Attachment?PartNumber=078.47522.0211
PC942 = SC1U16V3KX-5GP: CHIP CAP C 1U 16V K0603 X7R; GREENDFACTOR: R2_SA;HF_SA;G_SA;; Level: SMD; MAIN_SOURCE: M; Package Type: SMD-BCG3; Part Number: 78.10521.2BL; SPEC: http://wpqssvr.wistron.com.tw:7001/wpqs/servlet/COM.qpart.Attachment?PartNumber=78.10521.2BL; Status: POP
PC1055 = SC1U10V2KX-4-GP: CHIP CAP C 1U 10V K 0402 X6S; GREENDFACTOR: R2_SA;HF_SA;; Part Number: 78.10523.8FL; Part Type: SMD-BCG6; SPEC: http://wpqssvr.wistron.com.tw:7001/wpqs/servlet/COM.qpart.Attachment?PartNumber=78.10523.8FL
PD11 = PTZ5D6B-GP: DIODE ZEN PTZ5.6B 5.6V PMDS; GREENDFACTOR: R2_SA;; Package Type: DISCRET-G5; Part Number: 83.5R603.H3H; SPEC: http://wpqssvr.wistron.com.tw:7001/wpqs/servlet/COM.qpart.Attachment?PartNumber=83.5R603.H3H
PG64 = COPPER-CLOSE-GP-U: COPPER CLOSE; GREENDFACTOR: Regular;; Level: SMD; Package Type: DISCRET-G9; Part Number: ZZ.CON2C.XXX; Part Type: DISCRET-G9; SPEC: http://wpqssvr.wistron.com.tw:7001/wpqs/servlet/COM.qpart.Attachment?PartNumber=ZZ.CON2C.XXX
PL49 = IND-1UH-188-GP: CHIP IND 1UH M PCMB065T-1R0MS; GREENDFACTOR: R2_SA;; Package Type: DISCRET-G7; Part Number: 68.1R01E.10D; SPEC: http://wpqssvr.wistron.com.tw:7001/wpqs/servlet/COM.qpart.Attachment?PartNumber=68.1R01E.10D
PL50 = BLM21PG220SN1DGP: CHIP BEAD BLM21PG220SN1D (LF); GREENDFACTOR: R2_SA;HF_SA;; Level: SMD; Package Type: DISCRET-G; Part Number: 68.00084.831; Part Type: DISCRET-G; SPEC: http://wpqssvr.wistron.com.tw:7001/wpqs/servlet/COM.qpart.Attachment?PartNumber=68.00084.831
PR2 = 147KR2F-L-GP: CHIP RES 147K F 1/16W 0402; GREENDFACTOR: R2_SA;HF_SA;G_SA;; Part Number: 64.14735.L1L; Part Type: SMD-RG5; SPEC: http://wpqssvr.wistron.com.tw:7001/wpqs/servlet/COM.qpart.Attachment?PartNumber=64.14735.L1L
PR3 = 309KR2F-GP: CHIP RES 309K F 1/16W 0402; GREENDFACTOR: R2_SA;HF_SA;G_SA;; Package Type: SMD-RG; Part Number: 64.30935.6DL; SPEC: http://wpqssvr.wistron.com.tw:7001/wpqs/servlet/COM.qpart.Attachment?PartNumber=64.30935.6DL
PR4 = 309KR2F-GP: CHIP RES 309K F 1/16W 0402; GREENDFACTOR: R2_SA;HF_SA;G_SA;; POP?: NOPOP; Package Type: SMD-RG; Part Number: 64.30935.6DL; SPEC: http://wpqssvr.wistron.com.tw:7001/wpqs/servlet/COM.qpart.Attachment?PartNumber=64.30935.6DL
PR36 = 3K74R2F-GP: CHIP RES 3.74K F 1/16W 0402; GREENDFACTOR: R2_SA;HF_SA;G_SA;; Part Number: 64.37415.6DL; Part Type: RCL_GP; SPEC: http://wpqssvr.wistron.com.tw:7001/wpqs/servlet/COM.qpart.Attachment?PartNumber=64.37415.6DL
PR347 = 20KR2F-L-GP: CHIP RES 20K F 1/16W 0402; GREENDFACTOR: R2_SA;HF_SA;G_SA;; Part Number: 64.20025.6DL; Part Type: SMD-RG; SPEC: http://wpqssvr.wistron.com.tw:7001/wpqs/servlet/COM.qpart.Attachment?PartNumber=64.20025.6DL
PR441 PR638 = 10KR2F-2-GP: CHIP RES 10K F 1/16W 0402; GREENDFACTOR: R2_SA;HF_SA;G_SA;; Level: SMD; Package Type: SMD-RG; Part Number: 64.10025.6DL; Part Type: SMD-RG; SPEC: http://wpqssvr.wistron.com.tw:7001/wpqs/servlet/COM.qpart.Attachment?PartNumber=64.10025.6DL
PR481 = 2D7R3-GP: CHIP RES 2.7 J 1/10W 0603; GREENDFACTOR: R2_SA;HF_SA;G_SA;; Package Type: RCL_GP; Part Number: 63.2R734.15L; SPEC: http://wpqssvr.wistron.com.tw:7001/wpqs/servlet/COM.qpart.Attachment?PartNumber=63.2R734.15L
PR540 = 19K6R2F-GP: CHIP RES 19.6K F 1/16W 0402; GREENDFACTOR: R2_SA;HF_SA;G_SA;; Part Number: 64.19625.6DL; Part Type: SMD-RG; SPEC: http://wpqssvr.wistron.com.tw:7001/wpqs/servlet/COM.qpart.Attachment?PartNumber=64.19625.6DL
PR633 = 10R3F-GP: CHIP RES 10 F 1/10W 0603; GREENDFACTOR: R2_SA;HF_SA;G_SA;; Level: SMD; Package Type: RCL_GP; Part Number: 64.10R05.55L; Part Type: RCL_GP; SPEC: http://wpqssvr.wistron.com.tw:7001/wpqs/servlet/COM.qpart.Attachment?PartNumber=64.10R05.55L; Status: POP
PR635 = 45K3R2F-L-GP: CHIP RES 45.3K F 1/16W 0402; GREENDFACTOR: R2_SA;HF_SA;G_SA;; Package Type: SMD-RG; Part Number: 64.45325.6DL; SPEC: http://wpqssvr.wistron.com.tw:7001/wpqs/servlet/COM.qpart.Attachment?PartNumber=64.45325.6DL
PR640 = 2KR2F-3-GP: CHIP RES 2K F 1/16W 0402; GREENDFACTOR: R2_SA;HF_SA;G_SA;; Package Type: SMD-RG; Part Number: 64.20015.6DL; SPEC: http://wpqssvr.wistron.com.tw:7001/wpqs/servlet/COM.qpart.Attachment?PartNumber=64.20015.6DL
PR642 = 3D01R5F-GP: CHIP RES 3.01 F 1/8W 0805; GREENDFACTOR: R2_SA;HF_SA;G_SA;; Level: SMD; POP?: NOPOP; Package Type: SMD-RG5; Part Number: 64.3R015.16L; Part Type: SMD-RG5; SPEC: http://wpqssvr.wistron.com.tw:7001/wpqs/servlet/COM.qpart.Attachment?PartNumber=64.3R015.16L
PR649 = 2D2R3-1-U-GP: CHIP RES 2.2 F 1/10W 0603(ROHS; GREENDFACTOR: R2_SA;HF_SA;G_SA;; Package Type: RCL_GP; Part Number: 64.2R205.55L; SPEC: http://wpqssvr.wistron.com.tw:7001/wpqs/servlet/COM.qpart.Attachment?PartNumber=64.2R205.55L
PR817 = 0R2J-2-GP: CHIP RES 0 J 1/16W 0402; GREENDFACTOR: R2_SA;HF_SA;G_SA;; Level: SMD; Package Type: SMD-RG; Part Number: 63.R0034.1DL; Part Type: SMD-RG; ROOM: VR_CHIPSET; SPEC: http://wpqssvr.wistron.com.tw:7001/wpqs/servlet/COM.qpart.Attachment?PartNumber=63.R0034.1DL; Status: POP
PR2171 = 39K2R2F-L-GP: CHIP RES 39.2K F 1/16W 0402; GREENDFACTOR: R2_SA;HF_SA;G_SA;; POP?: NOPOP; Package Type: SMD-RG; Part Number: 64.39225.6DL; SPEC: http://wpqssvr.wistron.com.tw:7001/wpqs/servlet/COM.qpart.Attachment?PartNumber=64.39225.6DL
PR2172 = 39K2R2F-L-GP: CHIP RES 39.2K F 1/16W 0402; GREENDFACTOR: R2_SA;HF_SA;G_SA;; Package Type: SMD-RG; Part Number: 64.39225.6DL; SPEC: http://wpqssvr.wistron.com.tw:7001/wpqs/servlet/COM.qpart.Attachment?PartNumber=64.39225.6DL
PU54 = TPS53319DQPR-GP: IC PWR CTRL TPS53319DQPR QFN 22P; GREENDFACTOR: R2_SA;HF_SA;; Part Number: 74.53319.073; Part Type: DISCRET-G8; SPEC: http://wpqssvr.wistron.com.tw:7001/wpqs/servlet/COM.qpart.Attachment?PartNumber=74.53319.073

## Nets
AGND_P3V3: PG64.1 PR2.1 PR4.1 PR638.2 PR817.2 PR2171.1
GND: C1.2 C2.2 C3.2 C4.2 C5.2 C6.2 C7.2 C8.2 C9.2 C10.2 C11.2 C12.2 C13.2 C14.2 C15.2 C16.2 C17.2 C18.2 C19.2 C20.2 C21.2 C22.2 C23.2 C24.1 C25.2 C26.2 C27.2 C28.2 C29.2 C30.2 C31.2 C32.2 C33.2 C34.2 C35.2 C36.2 C37.2 C40.2 CN1.A1(PRSNT1#) CN1.A4(GND) CN1.A12(GND) CN1.A15(GND) CN1.A18(GND) CN1.A20(GND) CN1.A23(GND) CN1.A24(GND) CN1.A27(GND) CN1.A28(GND) CN1.A31(GND) CN1.A34(GND) CN1.A37(GND) CN1.A38(GND) CN1.A41(GND) CN1.A42(GND) CN1.A45(GND) CN1.A46(GND) CN1.A49(GND) CN1.B4(GND) CN1.B7(GND) CN1.B13(GND) CN1.B16(GND) CN1.B18(GND) CN1.B21(GND) CN1.B22(GND) CN1.B25(GND) CN1.B26(GND) CN1.B29(GND) CN1.B32(GND) CN1.B35(GND) CN1.B36(GND) CN1.B39(GND) CN1.B40(GND) CN1.B43(GND) CN1.B44(GND) CN1.B47(GND) CN1.B49(GND) CN2.A1(PRSNT1#) CN2.A4(GND) CN2.A12(GND) CN2.A15(GND) CN2.A18(GND) CN2.A20(GND) CN2.A23(GND) CN2.A24(GND) CN2.A27(GND) CN2.A28(GND) CN2.A31(GND) CN2.A34(GND) CN2.A37(GND) CN2.A38(GND) CN2.A41(GND) CN2.A42(GND) CN2.A45(GND) CN2.A46(GND) CN2.A49(GND) CN2.B4(GND) CN2.B7(GND) CN2.B13(GND) CN2.B16(GND) CN2.B18(GND) CN2.B21(GND) CN2.B22(GND) CN2.B25(GND) CN2.B26(GND) CN2.B29(GND) CN2.B32(GND) CN2.B35(GND) CN2.B36(GND) CN2.B39(GND) CN2.B40(GND) CN2.B43(GND) CN2.B44(GND) CN2.B47(GND) CN2.B49(GND) CN3.A1(PRSNT1#) CN3.A4(GND) CN3.A12(GND) CN3.A15(GND) CN3.A18(GND) CN3.A20(GND) CN3.A23(GND) CN3.A24(GND) CN3.A27(GND) CN3.A28(GND) CN3.A31(GND) CN3.A34(GND) CN3.A37(GND) CN3.A38(GND) CN3.A41(GND) CN3.A42(GND) CN3.A45(GND) CN3.A46(GND) CN3.A49(GND) CN3.B4(GND) CN3.B7(GND) CN3.B13(GND) CN3.B16(GND) CN3.B18(GND) CN3.B21(GND) CN3.B22(GND) CN3.B25(GND) CN3.B26(GND) CN3.B29(GND) CN3.B32(GND) CN3.B35(GND) CN3.B36(GND) CN3.B39(GND) CN3.B40(GND) CN3.B43(GND) CN3.B44(GND) CN3.B47(GND) CN3.B49(GND) CN4.1 CN4.2 GF1.A1 GF1.A4 GF1.A7 GF1.A12 GF1.A15 GF1.A18 GF1.A20 GF1.A23 GF1.A24 GF1.A27 GF1.A28 GF1.A31 GF1.A34 GF1.A37 GF1.A38 GF1.A41 GF1.A42 GF1.A45 GF1.A46 GF1.A49 GF1.A51 GF1.A54 GF1.A55 GF1.A58 GF1.A59 GF1.A62 GF1.A63 GF1.A66 GF1.A67 GF1.A70 GF1.A71 GF1.A74 GF1.A75 GF1.A78 GF1.A79 GF1.A82 GF1.A84 GF1.A87 GF1.A88 GF1.A91 GF1.A92 GF1.A95 GF1.A96 GF1.A99 GF1.A100 GF1.A103 GF1.A104 GF1.A107 GF1.A108 GF1.A111 GF1.A112 GF1.A115 GF1.B4 GF1.B7 GF1.B13 GF1.B16 GF1.B18 GF1.B21 GF1.B22 GF1.B25 GF1.B26 GF1.B29 GF1.B32 GF1.B35 GF1.B36 GF1.B39 GF1.B40 GF1.B43 GF1.B44 GF1.B47 GF1.B49 GF1.B52 GF1.B53 GF1.B56 GF1.B57 GF1.B60 GF1.B61 GF1.B64 GF1.B65 GF1.B68 GF1.B69 GF1.B72 GF1.B73 GF1.B76 GF1.B77 GF1.B80 GF1.B82 GF1.B85 GF1.B86 GF1.B89 GF1.B90 GF1.B93 GF1.B94 GF1.B97 GF1.B98 GF1.B101 GF1.B102 GF1.B105 GF1.B106 GF1.B109 GF1.B110 GF1.B113 H1.1 H2.1 H3.1 H3.2 H3.3 H3.4 H3.5 H3.6 H4.1 H4.2 H4.3 H4.4 H4.5 H4.6 PC790.2 PC792.2 PC793.2 PC794.2 PC795.2 PC836.2 PC904.2 PC905.2 PC906.2 PC907.2 PC908.2 PC909.2 PC911.2 PC941.2 PC942.1 PC1055.2 PD11.A(ANODE) PG64.2 PR36.2 PR347.1 PR642.2 PU54.23(GND) R2.2 R7.2 R8.1 R9.1 R10.2 R11.1 R12.2 R24.2 R26.1 R27.1 R28.1 R33.2 R35.2 TC1.2 TC2.2 TC3.2 U1.1(GND) U2.1(GND) U8.3(GND) U9.3(GND) U10.10(VSS) U13.3(GND)
P3V3: C5.1 C6.1 C7.1 C14.1 C15.1 C16.1 C31.1 C32.1 C33.1 C34.1 C35.1 C36.1 CN1.A9(+3.3V) CN1.A10(+3.3V) CN1.B8(+3.3V) CN2.A9(+3.3V) CN2.A10(+3.3V) CN2.B8(+3.3V) CN3.A9(+3.3V) CN3.A10(+3.3V) CN3.B8(+3.3V) PC790.1 PC792.1 PC793.1 PC794.1 PC795.1 PC836.1 PC908.1 PC909.1 PC919.1 PD11.K(CATHODE) PL49.2 PR633.1 TC2.1 TC3.1
P3V3_AUX: C8.1 C9.1 C17.1 C18.1 C20.1 C22.1 C24.2 C26.1 C27.1 C40.1 CN1.B10(3.3VAUX) CN2.B10(3.3VAUX) CN3.B10(3.3VAUX) GF1.B10 R13.2 R14.2 R15.2 R16.2 R17.2 R18.1 R19.1 R20.1 R21.1 R22.1 R23.1 R29.2 R30.2 R31.2 R36.1 R37.1 U8.5(VCC) U9.5(VCC) U10.20(VDD) U13.5(VCC)
P3V3_EN: PC1055.1 PR36.1 PR540.2 PU54.2(EN)
P3V3_LL: PC917.2 PC918.1 PL49.1 PR640.1 PU54.6(LL#6) PU54.7(LL#7) PU54.8(LL#8) PU54.9(LL#9) PU54.10(LL#10) PU54.11(LL#11)
P3V3_LL_R: PC485.1 PC919.2 PR640.2
P3V3_MB: GF1.A9 GF1.A10 GF1.B8
P3V3_MODE: PR2171.2 PR2172.1 PU54.20(MODE)
P3V3_PG: PR347.2 PR441.1 PR2172.2 PU54.3(PGOOD) U9.2(B)
P3V3_RF: PR3.2 PR4.2 PU54.22(RF)
P3V3_ROVP: PR817.1 PU54.5(ROVP)
P3V3_SNB: PC918.2 PR642.1
P3V3_TRIP: PR2.2 PU54.21(TRIP)
P3V3_VBST: PR481.1 PU54.4(VBST)
P3V3_VBST_RC: PC917.1 PR481.2
P3V3_VDD: PC941.1 PR649.2 PU54.19(VDD)
P3V3_VFB: PC485.2 PR635.2 PR638.1 PU54.1(VFB)
P3V3_VFB_R: PR633.2 PR635.1
P3V3_VIN: PC904.1 PC905.1 PC906.1 PC907.1 PC911.1 PL50.2 PU54.12(VIN) PU54.13(VIN) PU54.14(VIN) PU54.15(VIN) PU54.16(VIN) PU54.17(VIN)
P3V3_VREG: PC942.2 PR3.1 PR441.2 PU54.18(VREG)
P12V: C10.1 C11.1 C12.1 C13.1 C23.1 C25.1 C28.1 C29.1 C30.1 CN2.A2(+12V) CN2.A3(+12V) CN2.B1(+12V) CN2.B2(+12V) CN2.B3(+12V) CN3.A2(+12V) CN3.A3(+12V) CN3.B1(+12V) CN3.B2(+12V) CN3.B3(+12V) CN4.3 CN4.4 PL50.1 PR540.1 PR649.1 R5.1 TC1.1
P12V_MB: C1.1 C2.1 C3.1 C4.1 C21.1 CN1.A2(+12V) CN1.A3(+12V) CN1.B1(+12V) CN1.B2(+12V) CN1.B3(+12V) GF1.A2 GF1.A3 GF1.B1 GF1.B2 GF1.B3 R1.1
ADDR_0: R28.2 R29.1 U10.1(A0)
ADDR_1: R27.2 R30.1 U10.2(A1)
ADDR_2: R26.2 R31.1 U10.3(A2)
CLK100_PCIE_SLOT0_N: CN1.A14(REFCLK-) GF1.A14
CLK100_PCIE_SLOT0_P: CN1.A13(REFCLK+) GF1.A13
CLK100_PCIE_SLOT1_N: CN2.A14(REFCLK-) GF1.A33
CLK100_PCIE_SLOT1_P: CN2.A13(REFCLK+) GF1.A32
CLK100_PCIE_SLOT2_N: CN3.A14(REFCLK-) GF1.A6
CLK100_PCIE_SLOT2_P: CN3.A13(REFCLK+) GF1.A5
INTRPT: R17.1 U10.17(INT#)
INTRPT_0: R13.1 U10.4(INT0#)
INTRPT_1: R14.1 U10.7(INT1#)
INTRPT_2: R15.1 U10.11(INT2#)
INTRPT_3: R16.1 U10.14(INT3#)
LAN_SMB_ALERT_N: GF1.B12 RE4.2 RE5.2 RE11.2
LAN_SMB_CLK: GF1.B9 RE2.1 RE9.1 RE14.1
LAN_SMB_DAT: GF1.A8 RE3.1 RE10.1 RE15.1
PCH_PLTRST_N: GF1.A11 U13.2(B)
PCIE_SLOT0_CPRSNT1_N: CN1.B17(PRSNT2#B17) CN1.B31(PRSNT2#B31) GF1.B17
PCIE_SLOT0_CPRSNT2_N: CN1.B48(PRSNT2#B48) GF1.B31
PCIE_SLOT0_RXN0: CN1.A17(PERN0) GF1.A17
PCIE_SLOT0_RXN1: CN1.A22(PERN1) GF1.A22
PCIE_SLOT0_RXN2: CN1.A26(PERN2) GF1.A26
PCIE_SLOT0_RXN3: CN1.A30(PERN3) GF1.A30
PCIE_SLOT0_RXN4: CN1.A36(PERN4) GF1.A36
PCIE_SLOT0_RXN5: CN1.A40(PERN5) GF1.A40
PCIE_SLOT0_RXN6: CN1.A44(PERN6) GF1.A44
PCIE_SLOT0_RXN7: CN1.A48(PERN7) GF1.A48
PCIE_SLOT0_RXP0: CN1.A16(PERP0) GF1.A16
PCIE_SLOT0_RXP1: CN1.A21(PERP1) GF1.A21
PCIE_SLOT0_RXP2: CN1.A25(PERP2) GF1.A25
PCIE_SLOT0_RXP3: CN1.A29(PERP3) GF1.A29
PCIE_SLOT0_RXP4: CN1.A35(PERP4) GF1.A35
PCIE_SLOT0_RXP5: CN1.A39(PERP5) GF1.A39
PCIE_SLOT0_RXP6: CN1.A43(PERP6) GF1.A43
PCIE_SLOT0_RXP7: CN1.A47(PERP7) GF1.A47
PCIE_SLOT0_TXN0: CN1.B15(PETN0) GF1.B15
PCIE_SLOT0_TXN1: CN1.B20(PETN1) GF1.B20
PCIE_SLOT0_TXN2: CN1.B24(PETN2) GF1.B24
PCIE_SLOT0_TXN3: CN1.B28(PETN3) GF1.B28
PCIE_SLOT0_TXN4: CN1.B34(PETN4) GF1.B34
PCIE_SLOT0_TXN5: CN1.B38(PETN5) GF1.B38
PCIE_SLOT0_TXN6: CN1.B42(PETN6) GF1.B42
PCIE_SLOT0_TXN7: CN1.B46(PETN7) GF1.B46
PCIE_SLOT0_TXP0: CN1.B14(PETP0) GF1.B14
PCIE_SLOT0_TXP1: CN1.B19(PETP1) GF1.B19
PCIE_SLOT0_TXP2: CN1.B23(PETP2) GF1.B23
PCIE_SLOT0_TXP3: CN1.B27(PETP3) GF1.B27
PCIE_SLOT0_TXP4: CN1.B33(PETP4) GF1.B33
PCIE_SLOT0_TXP5: CN1.B37(PETP5) GF1.B37
PCIE_SLOT0_TXP6: CN1.B41(PETP6) GF1.B41
PCIE_SLOT0_TXP7: CN1.B45(PETP7) GF1.B45
PCIE_SLOT1_CPRSNT1_N: CN2.B17(PRSNT2#B17) CN2.B31(PRSNT2#B31) GF1.B48
PCIE_SLOT1_CPRSNT2_N: CN2.B48(PRSNT2#B48) GF1.B81
PCIE_SLOT1_RXN0: CN2.A17(PERN0) GF1.A53
PCIE_SLOT1_RXN1: CN2.A22(PERN1) GF1.A57
PCIE_SLOT1_RXN2: CN2.A26(PERN2) GF1.A61
PCIE_SLOT1_RXN3: CN2.A30(PERN3) GF1.A65
PCIE_SLOT1_RXN4: CN2.A36(PERN4) GF1.A69
PCIE_SLOT1_RXN5: CN2.A40(PERN5) GF1.A73
PCIE_SLOT1_RXN6: CN2.A44(PERN6) GF1.A77
PCIE_SLOT1_RXN7: CN2.A48(PERN7) GF1.A81
PCIE_SLOT1_RXP0: CN2.A16(PERP0) GF1.A52
PCIE_SLOT1_RXP1: CN2.A21(PERP1) GF1.A56
PCIE_SLOT1_RXP2: CN2.A25(PERP2) GF1.A60
PCIE_SLOT1_RXP3: CN2.A29(PERP3) GF1.A64
PCIE_SLOT1_RXP4: CN2.A35(PERP4) GF1.A68
PCIE_SLOT1_RXP5: CN2.A39(PERP5) GF1.A72
PCIE_SLOT1_RXP6: CN2.A43(PERP6) GF1.A76
PCIE_SLOT1_RXP7: CN2.A47(PERP7) GF1.A80
PCIE_SLOT1_TXN0: CN2.B15(PETN0) GF1.B51
PCIE_SLOT1_TXN1: CN2.B20(PETN1) GF1.B55
PCIE_SLOT1_TXN2: CN2.B24(PETN2) GF1.B59
PCIE_SLOT1_TXN3: CN2.B28(PETN3) GF1.B63
PCIE_SLOT1_TXN4: CN2.B34(PETN4) GF1.B67
PCIE_SLOT1_TXN5: CN2.B38(PETN5) GF1.B71
PCIE_SLOT1_TXN6: CN2.B42(PETN6) GF1.B75
PCIE_SLOT1_TXN7: CN2.B46(PETN7) GF1.B79
PCIE_SLOT1_TXP0: CN2.B14(PETP0) GF1.B50
PCIE_SLOT1_TXP1: CN2.B19(PETP1) GF1.B54
PCIE_SLOT1_TXP2: CN2.B23(PETP2) GF1.B58
PCIE_SLOT1_TXP3: CN2.B27(PETP3) GF1.B62
PCIE_SLOT1_TXP4: CN2.B33(PETP4) GF1.B66
PCIE_SLOT1_TXP5: CN2.B37(PETP5) GF1.B70
PCIE_SLOT1_TXP6: CN2.B41(PETP6) GF1.B74
PCIE_SLOT1_TXP7: CN2.B45(PETP7) GF1.B78
PCIE_SLOT2_CPRSNT1_N: CN3.B17(PRSNT2#B17) CN3.B31(PRSNT2#B31) GF1.B114
PCIE_SLOT2_CPRSNT2_N: CN3.B48(PRSNT2#B48) GF1.B115
PCIE_SLOT2_RXN0: CN3.A17(PERN0) GF1.A86
PCIE_SLOT2_RXN1: CN3.A22(PERN1) GF1.A90
PCIE_SLOT2_RXN2: CN3.A26(PERN2) GF1.A94
PCIE_SLOT2_RXN3: CN3.A30(PERN3) GF1.A98
PCIE_SLOT2_RXN4: CN3.A36(PERN4) GF1.A102
PCIE_SLOT2_RXN5: CN3.A40(PERN5) GF1.A106
PCIE_SLOT2_RXN6: CN3.A44(PERN6) GF1.A110
PCIE_SLOT2_RXN7: CN3.A48(PERN7) GF1.A114
PCIE_SLOT2_RXP0: CN3.A16(PERP0) GF1.A85
PCIE_SLOT2_RXP1: CN3.A21(PERP1) GF1.A89
PCIE_SLOT2_RXP2: CN3.A25(PERP2) GF1.A93
PCIE_SLOT2_RXP3: CN3.A29(PERP3) GF1.A97
PCIE_SLOT2_RXP4: CN3.A35(PERP4) GF1.A101
PCIE_SLOT2_RXP5: CN3.A39(PERP5) GF1.A105
PCIE_SLOT2_RXP6: CN3.A43(PERP6) GF1.A109
PCIE_SLOT2_RXP7: CN3.A47(PERP7) GF1.A113
PCIE_SLOT2_TXN0: CN3.B15(PETN0) GF1.B84
PCIE_SLOT2_TXN1: CN3.B20(PETN1) GF1.B88
PCIE_SLOT2_TXN2: CN3.B24(PETN2) GF1.B92
PCIE_SLOT2_TXN3: CN3.B28(PETN3) GF1.B96
PCIE_SLOT2_TXN4: CN3.B34(PETN4) GF1.B100
PCIE_SLOT2_TXN5: CN3.B38(PETN5) GF1.B104
PCIE_SLOT2_TXN6: CN3.B42(PETN6) GF1.B108
PCIE_SLOT2_TXN7: CN3.B46(PETN7) GF1.B112
PCIE_SLOT2_TXP0: CN3.B14(PETP0) GF1.B83
PCIE_SLOT2_TXP1: CN3.B19(PETP1) GF1.B87
PCIE_SLOT2_TXP2: CN3.B23(PETP2) GF1.B91
PCIE_SLOT2_TXP3: CN3.B27(PETP3) GF1.B95
PCIE_SLOT2_TXP4: CN3.B33(PETP4) GF1.B99
PCIE_SLOT2_TXP5: CN3.B37(PETP5) GF1.B103
PCIE_SLOT2_TXP6: CN3.B41(PETP6) GF1.B107
PCIE_SLOT2_TXP7: CN3.B45(PETP7) GF1.B111
PCIE_SMCLK: GF1.B5 U10.18(SCL)
PCIE_SMCLK0: R18.2 RE1.2 U10.6(SC0)
PCIE_SMCLK1: R19.2 RE6.2 U10.9(SC1)
PCIE_SMCLK2: R20.2 RE12.2 U10.13(SC2)
PCIE_SMDAT: GF1.B6 U10.19(SDA)
PCIE_SMDAT0: R21.2 RE7.2 U10.5(SD0)
PCIE_SMDAT1: R22.2 RE8.2 U10.8(SD1)
PCIE_SMDAT2: R23.2 RE13.2 U10.12(SD2)
PCIE_WAKE_N: CN1.B11(WAKE#) CN2.B11(WAKE#) CN3.B11(WAKE#) GF1.B11
PERST_O_1_R: R3.2 R37.2 U8.1(A)
PERST_O_2_R: R4.2 R36.2 U9.1(A)
PERST_P12V_MB_Y_N: R41.1 U8.4(Y)
PERST_P12V_R_N: R41.2 R42.2 U13.1(A)
PERST_P12V_Y_N: R42.1 U8.2(B) U9.4(Y)
PERST_SLOT0_N: CN1.A11(PERST#) R39.2
PERST_SLOT1_N: CN2.A11(PERST#) R38.2
PERST_SLOT2_N: CN3.A11(PERST#) R40.2
PERST_SLOT_N: R38.1 R39.1 R40.1 U13.4(Y)
RESET_O_1: R3.1 U1.2(RESET#)
RESET_O_2: R4.1 U2.2(RESET#)
RESET_P12V_IN: C37.1 R5.2 R24.1 U2.3(VDD)
RESET_P12V_MB_IN: C19.1 R1.2 R2.1 U1.3(VDD)
RSVD0: GF1.B30 TP6.1
RSVD1: GF1.A19 TP7.1
S0_PCIE_SMCLK: CN1.B5(SMCLK) RE1.1
S0_PCIE_SMDAT: CN1.B6(SMDAT) RE7.1
S0_SMB_ALERT_B12_N: CN1.B12(RSVD#B12) RE4.1
S0_SMB_CLK_A32: CN1.A32(RSVD#A32) RE2.2
S0_SMB_DAT_A33: CN1.A33(RSVD#A33) RE3.2
S1_PCIE_SMCLK: CN2.B5(SMCLK) RE6.1
S1_PCIE_SMDAT: CN2.B6(SMDAT) RE8.1
S1_SMB_ALERT_B12_N: CN2.B12(RSVD#B12) RE5.1
S1_SMB_CLK_A32: CN2.A32(RSVD#A32) RE9.2
S1_SMB_DAT_A33: CN2.A33(RSVD#A33) RE10.2
S2_PCIE_SMCLK: CN3.B5(SMCLK) RE12.1
S2_PCIE_SMDAT: CN3.B6(SMDAT) RE13.1
S2_SMB_ALERT_B12_N: CN3.B12(RSVD#B12) RE11.1
S2_SMB_CLK_A32: CN3.A32(RSVD#A32) RE14.2
S2_SMB_DAT_A33: CN3.A33(RSVD#A33) RE15.2
SLOT0_CONFIG: GF1.A50 R33.1
SLOT0_ID_0: CN1.A19(RSVD#A19) R7.1
SLOT0_ID_1: CN1.B30(RSVD#B30) R8.2
SLOT1_CONFIG: GF1.A83 R35.1
SLOT1_ID_0: CN2.A19(RSVD#A19) R10.1
SLOT1_ID_1: CN2.B30(RSVD#B30) R9.2
SLOT2_ID_0: CN3.A19(RSVD#A19) R12.1
SLOT2_ID_1: CN3.B30(RSVD#B30) R11.2

Not connected (* = marked no-connect by the designer): CN1 A5(JTAG2)* A6(JTAG3)* A7(JTAG4)* A8(JTAG5)* B9(JTAG1)* NP1* NP2*; CN2 A5(JTAG2)* A6(JTAG3)* A7(JTAG4)* A8(JTAG5)* B9(JTAG1)* NP1* NP2*; CN3 A5(JTAG2)* A6(JTAG3)* A7(JTAG4)* A8(JTAG5)* B9(JTAG1)* NP1* NP2*; U10 15(SD3)* 16(SC3)*

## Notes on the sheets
sheet 1
- HISTORY
- 2016/07/04
  Reference 15703-SA
  Added screw hold
sheet 2
- Power rail : P3V3
  Controller : TPS53319 (Fswitching=750KHz)
  TDC : 10.4A
  MAX : 10.4A
  OCP : 13A
- vender P/N:PCMB065T-1R0MS
  DCR:5.6m ohm max:6.5m ohm
  Idc:13A  Isat:15A
  Dimensions:7.05 * 6.6 * 4.8 (mm)
- SS=1ms
- FCCM Mode
- OCP =13A
- FS=750KHz
sheet 3
- I2C-BUS MULTIPLEXER
- SMBUS Address 0xE2
sheet 4
- PCIE X24 RISER GF
- VIL=2.87 2.93 2.99
- Ra
- 0.5%
- AND GATE
- VCC + 0.5 V
  0.05mW
- Rb
- 0.5%
- AND GATE
- AND GATE
- AND GATE
sheet 5
- PCIE X8 RISER SLOT4
sheet 6
- PCIE X8 RISER SLOT3
sheet 7
- PCIE X8 RISER SLOT2
sheet 8
- STACKUP
sheet 9
- BLOCK DIAGRAM
- PCIE x8 CONNECTOR (SLOT4)
- Power connector
- page. 8
- P12V
- P3V3
- page. 6
- PCIE x8 CONNECTOR (SLOT3)
- page. 9
- POL power circuit
- page. 5
- P3V3
- PCIE x8 CONNECTOR (SLOT2)
- page. 4
- P3V3
- P12V_MB
- P3V3_AUX
- PCIe x24 CONNECTOR ON MB
sheet 10
- Wiwynn Corporation
- Code Name: LEOPARD BW CHANNEL 3 SLOT PCIE RISER
  PCB No.: 16366
  PCB P/N:
  Version: SA
  Date: 2016/07/04
  PCB Thinkness: 1.57mm
  Layer counter: 6 Layers
- WIWYNN CONFIDENTIAL
